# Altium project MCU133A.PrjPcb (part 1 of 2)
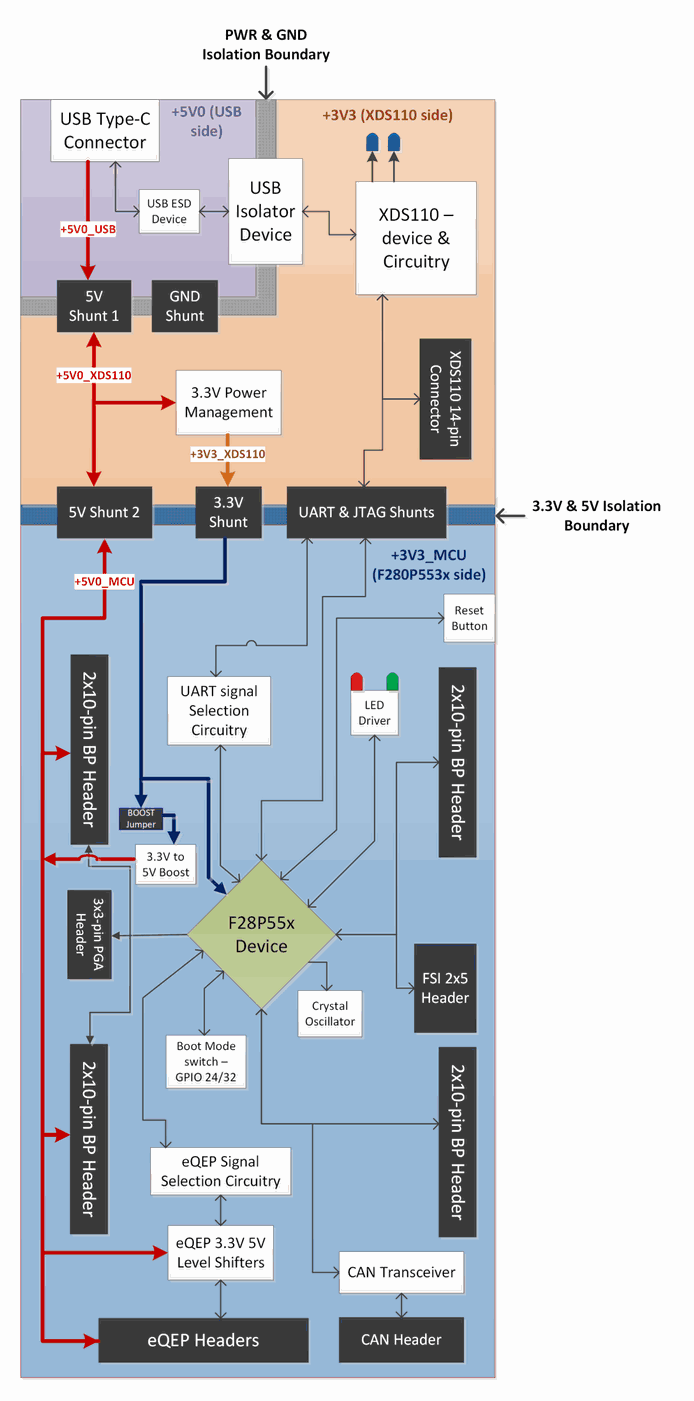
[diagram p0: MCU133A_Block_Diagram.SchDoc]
CopyrightYear: 2024; DrawnBy: Stevan Duraskovic; EVM_orderable: LAUNCHXL-F28P55X; PCB_Layout: a0507455; PCB_Rev: A; PRJ_Customer: Public Release; PRJ_Engineer: Stevan Duraskovic; PRJ_Number: MCU133; PRJ_Title: LAUNCHXL-F28P55X; SCH_Rev: A; TechSupport: http://www.ti.com/support; TID: N/A
8 sheets, 279 parts. Net scope: global (net labels, ports and power ports of the same name join across sheets).
Board file: MCU133A.PcbDoc
Sheets:
  MCU133A_Block_Diagram.SchDoc
  MCU133A_Connectors.SchDoc
  MCU133A_AltRouting_Misc.SchDoc
  MCU133A_F28P55x_Device.SchDoc
  MCU133A_ADC.SchDoc
  MCU133A_USB_and_Power.SchDoc
  MCU133A_XDS110_MCU.SchDoc
  MCU133A_Hardware.SchDoc

## Sheet MCU133A_Block_Diagram.SchDoc
size 431 x 279 mm; Date: Not shown in title block; ApprovedBy: Not shown in title block; CheckedBy: Not shown in title block; Author: Not shown in title block; CompanyName: Not shown in title block; Engineer: Not shown in title block; Organization: Not shown in title block; Address1: Not shown in title block; Address2: Not shown in title block; Address3: Not shown in title block; Address4: Not shown in title block; DocumentNumber: 1; Revision: Use project parameter SCH_Rev; SheetNumber: 1; SheetTotal: 8; PageSetup: Record=PageOptions¦CenterHorizontal=True¦CenterVertical=True¦PrintScale=1.00¦XCorrection=1.00¦YCorrection=1.00¦PrintKind=0¦BorderSize=5000000¦LeftOffset=0¦BottomOffset=0¦Orientation=2¦PaperLength=1000¦PaperWidth=1000¦Scale=100¦PaperSource=15¦PrintQuality=600¦MediaType=1¦DitherType=10¦PaperKind=Letter¦PrintScaleMode=1

## Sheet MCU133A_Connectors.SchDoc
size 431 x 279 mm; Date: Not shown in title block; ApprovedBy: Not shown in title block; CheckedBy: Not shown in title block; Author: Not shown in title block; CompanyName: Not shown in title block; Engineer: Not shown in title block; Organization: Not shown in title block; Address1: Not shown in title block; Address2: Not shown in title block; Address3: Not shown in title block; Address4: Not shown in title block; DocumentNumber: 2; Revision: Use project parameter SCH_Rev; SheetNumber: 2; SheetTotal: 8; PageSetup: Record=PageOptions¦CenterHorizontal=True¦CenterVertical=True¦PrintScale=1.00¦XCorrection=1.00¦YCorrection=1.00¦PrintKind=0¦BorderSize=5000000¦LeftOffset=0¦BottomOffset=0¦Orientation=2¦PaperLength=1000¦PaperWidth=1000¦Scale=100¦PaperSource=15¦PrintQuality=600¦MediaType=1¦DitherType=10¦PaperKind=Letter¦PrintScaleMode=1
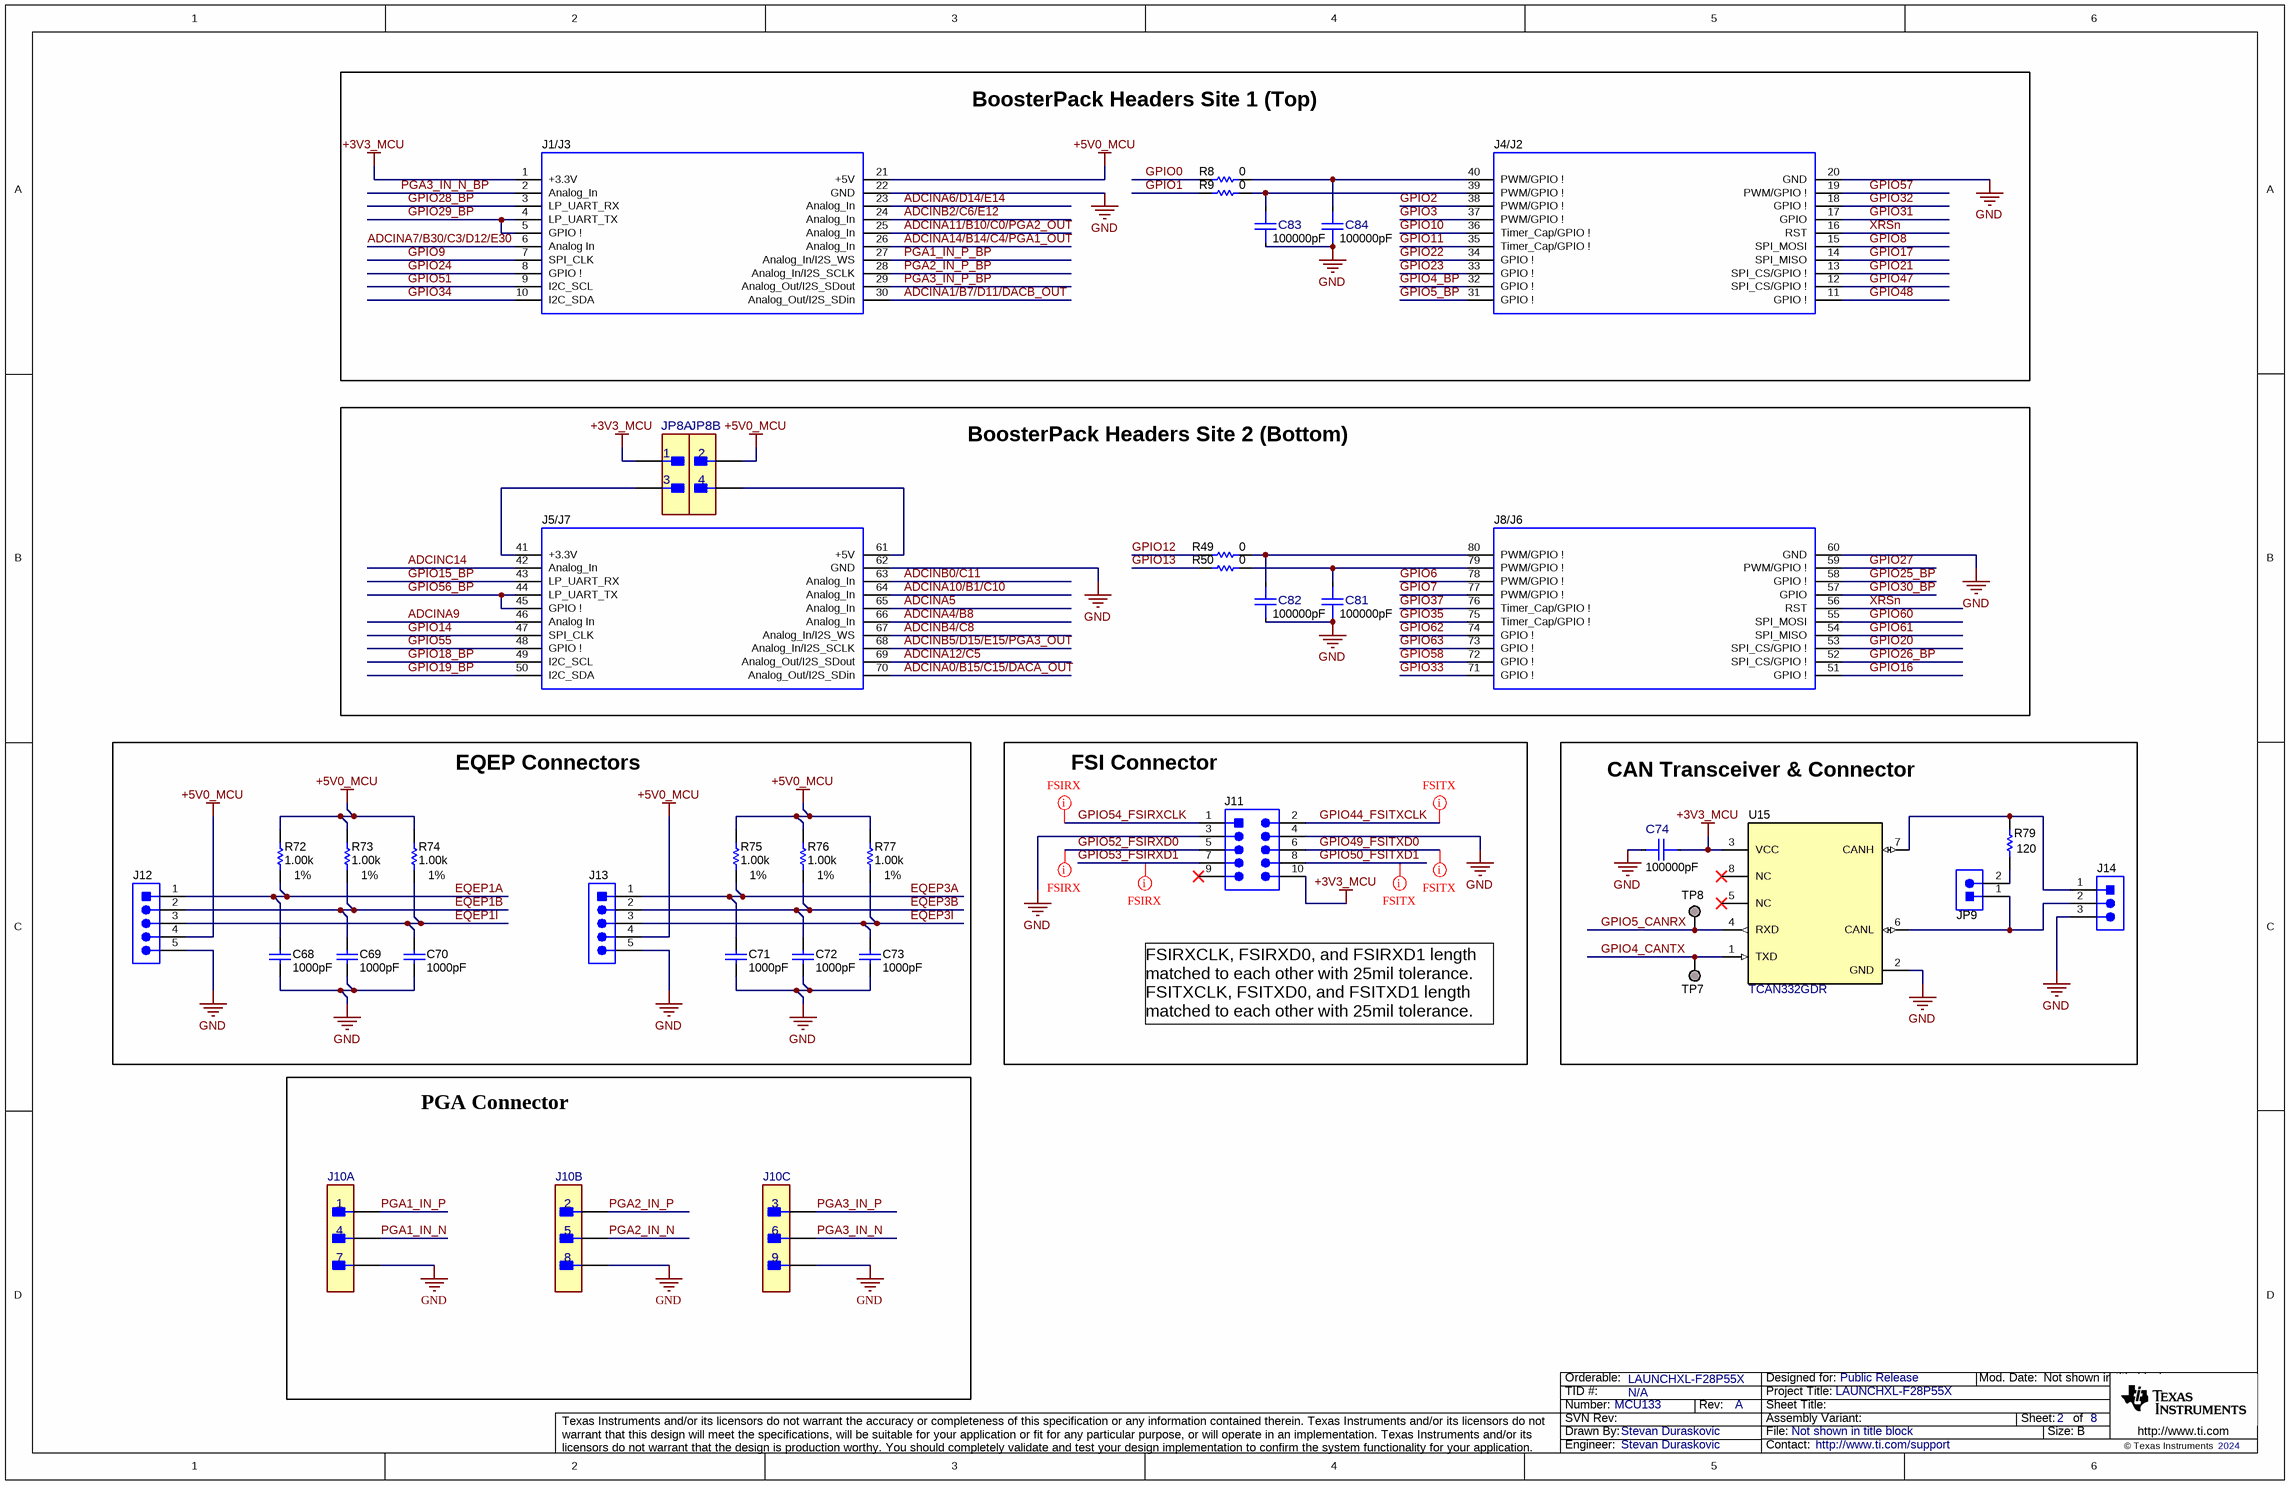
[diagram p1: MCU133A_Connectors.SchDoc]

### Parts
C68  ValueDisplayed: 1000pF  [0402]  (hidden comment: 885012205061)
C69  ValueDisplayed: 1000pF  [0402]  (hidden comment: 885012205061)
C70  ValueDisplayed: 1000pF  [0402]  (hidden comment: 885012205061)
C71  ValueDisplayed: 1000pF  [0402]  (hidden comment: 885012205061)
C72  ValueDisplayed: 1000pF  [0402]  (hidden comment: 885012205061)
C73  ValueDisplayed: 1000pF  [0402]  (hidden comment: 885012205061)
C74  ValueDisplayed: 100000pF  [FP-885012205018_0402-MFG]  (hidden comment: 885012205018)
C81  ValueDisplayed: 100000pF  [FP-885012205018_0402-MFG]  (hidden comment: 885012205018)
C82  ValueDisplayed: 100000pF  [FP-885012205018_0402-MFG]  (hidden comment: 885012205018)
C83  ValueDisplayed: 100000pF  [FP-885012205018_0402-MFG]  (hidden comment: 885012205018)
C84  ValueDisplayed: 100000pF  [FP-885012205018_0402-MFG]  (hidden comment: 885012205018)
J1/J3  SSQ-110-03-T-D  [BoosterPack_40pin_J1J3]  (value not drawn)
J4/J2  SSQ-110-03-T-D  [BoosterPack_40pin_J2J4]  (value not drawn)
J5/J7  SSQ-110-03-T-D  [BoosterPack_40pin_J5J7]  (value not drawn)
J8/J6  SSQ-110-03-T-D  [BoosterPack_40pin_J6J8]  (value not drawn)
J10  TSW-103-07-G-T  [FP-TSW-103-07-G-T_HDR9-MFG]  (value not drawn)  (parts A,B,C of 3)
J11  61301021121  [WURTH_61301021121]  (value not drawn)
J12  61300511121  [Wurth_61300511121]  (value not drawn)
J13  61300511121  [Wurth_61300511121]  (value not drawn)
J14  61300311121  [WURTH_61300311121]  (value not drawn)
JP8  61300421121  [FP-61300421121_HDR4-MFG]  (value not drawn)  (parts A,B of 2)
JP9  61300211121  [WURTH_61300211121]  (value not drawn)
R8  ValueDisplayed: 0  [0402]  (hidden comment: RC0402JR-070RL)
R9  ValueDisplayed: 0  [0402]  (hidden comment: RC0402JR-070RL)
R49  ValueDisplayed: 0  [0402]  (hidden comment: RC0402JR-070RL)
R50  ValueDisplayed: 0  [0402]  (hidden comment: RC0402JR-070RL)
R72  ValueDisplayed: 1.00k  Value1: 1%  [0402]  (hidden comment: CRCW04021K00FKED)
R73  ValueDisplayed: 1.00k  Value1: 1%  [0402]  (hidden comment: CRCW04021K00FKED)
R74  ValueDisplayed: 1.00k  Value1: 1%  [0402]  (hidden comment: CRCW04021K00FKED)
R75  ValueDisplayed: 1.00k  Value1: 1%  [0402]  (hidden comment: CRCW04021K00FKED)
R76  ValueDisplayed: 1.00k  Value1: 1%  [0402]  (hidden comment: CRCW04021K00FKED)
R77  ValueDisplayed: 1.00k  Value1: 1%  [0402]  (hidden comment: CRCW04021K00FKED)
R79  RC0603FR-07120RL  [0603]  (value not drawn)
TP7  TESTPOINT  [TP_50MIL-25MILHOLE]  (value not drawn)  (no BOM)
TP8  TESTPOINT  [TP_50MIL-25MILHOLE]  (value not drawn)  (no BOM)
U15  TCAN332GDR  [D0008A_N]

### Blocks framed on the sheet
BoosterPack Headers Site 1 (Top): C83 C84 J1/J3 J4/J2 R8 R9
BoosterPack Headers Site 2 (Bottom): C81 C82 J5/J7 J8/J6 JP8 R49 R50
EQEP Connectors: C68-C73 J12 J13 R72-R77
FSI Connector: J11
CAN Transceiver & Connector: C74 J14 JP9 R79 TP7 TP8 U15

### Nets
+3V3_MCU: C74.1 J1/J3.1(+3.3V) J11.10 JP8.1 U15.3(VCC)
+5V0_MCU: J1/J3.21(+5V) J12.4 J13.4 JP8.2 R72.2 R73.2 R74.2 R75.2 R76.2 R77.2
GND: C68.2 C69.2 C70.2 C71.2 C72.2 C73.2 C74.2 C81.1 C82.1 C83.1 C84.1 J1/J3.22(GND) J4/J2.20(GND) J5/J7.62(GND) J8/J6.60(GND) J10.7 J10.8 J10.9 J11.3 J11.4 J12.5 J13.5 J14.3 U15.2(GND)
ADCINA0/B15/C15/DACA_OUT: J5/J7.70(Analog_Out/I2S_SDin)
ADCINA1/B7/D11/DACB_OUT: J1/J3.30(Analog_Out/I2S_SDin)
ADCINA4/B8: J5/J7.66(Analog_In)
ADCINA5: J5/J7.65(Analog_In)
ADCINA6/D14/E14: J1/J3.23(Analog_In)
ADCINA7/B30/C3/D12/E30: J1/J3.6(Analog_In)
ADCINA9: J5/J7.46(Analog_In)
ADCINA10/B1/C10: J5/J7.64(Analog_In)
ADCINA11/B10/C0/PGA2_OUT: J1/J3.25(Analog_In)
ADCINA12/C5: J5/J7.69(Analog_Out/I2S_SDout)
ADCINA14/B14/C4/PGA1_OUT: J1/J3.26(Analog_In)
ADCINB0/C11: J5/J7.63(Analog_In)
ADCINB2/C6/E12: J1/J3.24(Analog_In)
ADCINB4/C8: J5/J7.67(Analog_In/I2S_WS)
ADCINB5/D15/E15/PGA3_OUT: J5/J7.68(Analog_In/I2S_SCLK)
ADCINC14: J5/J7.42(Analog_In)
EQEP1A: C68.1 J12.1 R72.1
EQEP1B: C69.1 J12.2 R73.1
EQEP1I: C70.1 J12.3 R74.1
EQEP3A: C71.1 J13.1 R75.1
EQEP3B: C72.1 J13.2 R76.1
EQEP3I: C73.1 J13.3 R77.1
GPIO0: R8.1
GPIO1: R9.1
GPIO2: J4/J2.38(PWM/GPIO_!)
GPIO3: J4/J2.37(PWM/GPIO_!)
GPIO4_BP: J4/J2.32(GPIO_!)
GPIO4_CANTX: TP7.1 U15.1(TXD)
GPIO5_BP: J4/J2.31(GPIO_!)
GPIO5_CANRX: TP8.1 U15.4(RXD)
GPIO6: J8/J6.78(PWM/GPIO_!)
GPIO7: J8/J6.77(PWM/GPIO_!)
GPIO8: J4/J2.15(SPI_MOSI)
GPIO9: J1/J3.7(SPI_CLK)
GPIO10: J4/J2.36(Timer_Cap/GPIO_!)
GPIO11: J4/J2.35(Timer_Cap/GPIO_!)
GPIO12: R49.1
GPIO13: R50.1
GPIO14: J5/J7.47(SPI_CLK)
GPIO15_BP: J5/J7.43(LP_UART_RX)
GPIO16: J8/J6.51(GPIO_!)
GPIO17: J4/J2.14(SPI_MISO)
GPIO18_BP: J5/J7.49(I2C_SCL)
GPIO19_BP: J5/J7.50(I2C_SDA)
GPIO20: J8/J6.53(SPI_CS/GPIO_!)
GPIO21: J4/J2.13(SPI_CS/GPIO_!)
GPIO22: J4/J2.34(GPIO_!)
GPIO23: J4/J2.33(GPIO_!)
GPIO24: J1/J3.8(GPIO_!)
GPIO25_BP: J8/J6.58(GPIO_!)
GPIO26_BP: J8/J6.52(SPI_CS/GPIO_!)
GPIO27: J8/J6.59(PWM/GPIO_!)
GPIO28_BP: J1/J3.3(LP_UART_RX)
GPIO29_BP: J1/J3.4(LP_UART_TX) J1/J3.5(GPIO_!)
GPIO30_BP: J8/J6.57(GPIO)
GPIO31: J4/J2.17(GPIO)
GPIO32: J4/J2.18(GPIO_!)
GPIO33: J8/J6.71(GPIO_!)
GPIO34: J1/J3.10(I2C_SDA)
GPIO35: J8/J6.75(Timer_Cap/GPIO_!)
GPIO37: J8/J6.76(Timer_Cap/GPIO_!)
GPIO44_FSITXCLK: J11.2
GPIO47: J4/J2.12(SPI_CS/GPIO_!)
GPIO48: J4/J2.11(GPIO_!)
GPIO49_FSITXD0: J11.6
GPIO50_FSITXD1: J11.8
GPIO51: J1/J3.9(I2C_SCL)
GPIO52_FSIRXD0: J11.5
GPIO53_FSIRXD1: J11.7
GPIO54_FSIRXCLK: J11.1
GPIO55: J5/J7.48(GPIO_!)
GPIO56_BP: J5/J7.44(LP_UART_TX) J5/J7.45(GPIO_!)
GPIO57: J4/J2.19(PWM/GPIO_!)
GPIO58: J8/J6.72(GPIO_!)
GPIO60: J8/J6.55(SPI_MOSI)
GPIO61: J8/J6.54(SPI_MISO)
GPIO62: J8/J6.74(GPIO_!)
GPIO63: J8/J6.73(GPIO_!)
PGA1_IN_N: J10.4
PGA1_IN_P: J10.1
PGA1_IN_P_BP: J1/J3.27(Analog_In/I2S_WS)
PGA2_IN_N: J10.5
PGA2_IN_P: J10.2
PGA2_IN_P_BP: J1/J3.28(Analog_In/I2S_SCLK)
PGA3_IN_N: J10.6
PGA3_IN_N_BP: J1/J3.2(Analog_In)
PGA3_IN_P: J10.3
PGA3_IN_P_BP: J1/J3.29(Analog_Out/I2S_SDout)
XRSn: J4/J2.16(RST) J8/J6.56(RST)
NetC81_2: C81.2 J8/J6.79(PWM/GPIO_!) R50.2
NetC82_2: C82.2 J8/J6.80(PWM/GPIO_!) R49.2
NetC83_2: C83.2 J4/J2.39(PWM/GPIO_!) R9.2
NetC84_2: C84.2 J4/J2.40(PWM/GPIO_!) R8.2
NetJ5/J7_41: J5/J7.41(+3.3V) JP8.3
NetJ5/J7_61: J5/J7.61(+5V) JP8.4
NetJ14_1: J14.1 R79.2 U15.7(CANH)
NetJ14_2: J14.2 JP9.1 U15.6(CANL)
NetJP9_2: JP9.2 R79.1

Not connected (* = marked no-connect by the designer): J11 9*; U15 5(NC)* 8(NC)*

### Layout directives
net class FSIRX: GPIO52_FSIRXD0, GPIO53_FSIRXD1, GPIO54_FSIRXCLK
net class FSITX: GPIO44_FSITXCLK, GPIO49_FSITXD0, GPIO50_FSITXD1

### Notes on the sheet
- (near R79) 120
- FSIRXCLK, FSIRXD0, and FSIRXD1 length matched to each other with 25mil tolerance.
  FSITXCLK, FSITXD0, and FSITXD1 length matched to each other with 25mil tolerance.
- PGA Connector

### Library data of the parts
C68-C73 = CMP-0006231-2: CAP, CERM, 1000 pF, 50 V, +/- 10%, X7R, 0402; Manufacturer: Wurth Elektronik; Polarized: N; Value: 1000pF; U/M: EA; Cap_F: 1nF; Value1: Unknown; VDC_V: 50V; TaMin_C: -55°C; TaMax_C: 125°C; SizeArea_mm2: 0.5; SizeAreaWB_mm2: 3; SizeX_mm: 1; SizeZ_mm: 0.6; AEC Category: Q200
C74 C81-C84 = CMP-0090362-1: 0.1µF ±10% 10V Ceramic Capacitor X7R 0402 (1005 Metric); Manufacturer: Wurth Electronics; AEC Qualified: No; Value: 100nF; SizeZ_mm: 0.55mm; TempCo: 15%
J1/J3 = CMP-0003837-4: Receptacle, 2.54mm, 10x2, Tin, TH; Alternate PartNumber: CRD-081413-A-G; Manufacturer: Samtec; Alternate Manufacturer: Major League Electronics; Note: Booster Pack 40 pin J1 and J3; Green_Lifecycle: Active; Green_REACh: Incomplete
J4/J2 = CMP-0078266-4: Receptacle, 2.54mm, 10x2, Tin, TH; Alternate PartNumber: CRD-081413-A-G; Manufacturer: Samtec; Alternate Manufacturer: Major League Electronics; Note: Booster Pack 40 pin J2 and J4; Green_REACh: Incomplete; Green_Lifecycle: Active
J5/J7 = CMP-0081070-3: Receptacle, 2.54mm, 10x2, Tin, TH; Alternate PartNumber: CRD-081413-A-G; Manufacturer: Samtec; Alternate Manufacturer: Major League Electronics; Note: Booster Pack 40 pin J5 and J7; Green_REACh: Incomplete; Green_Lifecycle: Active
J8/J6 = CMP-0081071-3: Receptacle, 2.54mm, 10x2, Tin, TH; Alternate PartNumber: CRD-081413-A-G; Manufacturer: Samtec; Alternate Manufacturer: Major League Electronics; Note: Booster Pack 40 pin J6 and J8; Green_REACh: Incomplete; Green_Lifecycle: Active
J10 = CMP-0090263-1: Manufacturer: Samtec; Conn Gender: Male; AEC Qualified: No; Conn Orientation: Straight; DUT-Pitch_mm: 2.54mm; Row_Count: 3; SizeZ_mm: 8.64mm; ContactFinish: Gold,Nickel
J11 = CMP-0054806-3: Header, 2.54 mm, 5x2, Gold, TH; Manufacturer: Wurth Elektronik; Green_Lifecycle: Active; Green_REACh: Passed; Cert_UL: Y; Current_A: 3A; Gender: Male; Pitch_mm: 2.54; Row_Count: 2; Shrouded: N; Voltage_V: 250V
J12 J13 = CMP-0084909-1: Header, 2.54mm, 5x1, Gold, TH; Manufacturer: Wurth Elektronik; Pitch_mm: 2.54; Gender: Male; Row_Count: 1; Shrouded: N; Current_A: 3A; Voltage_V: 250V
J14 = CMP-0054796-1: Header, 2.54 mm, 3x1, Gold, TH; Manufacturer: Wurth Elektronik; Green_Lifecycle: Active; Green_REACh: Passed; CNHeader: TRUE; CT: FALSE
JP8 = CMP-0092422-1: THT Vertical Pin Header WR-PHD, Pitch 2.54 mm, Dual Row, 4 pins; Manufacturer: Wurth Electronics; DUT-Pitch_mm: 2.54mm; SizeZ_mm: 8.89mm; Voltage_V: 250V; Conn Gender: Male; AEC Qualified: No; Row_Count: 2; ContactFinish: Gold; Conn Orientation: Straight; Current_A: 3A
JP9 = CMP-0054794-1: Header, 2.54 mm, 2x1, Gold, TH; Manufacturer: Wurth Elektronik; Green_Lifecycle: Active; Green_REACh: Passed; CNHeader: TRUE; CT: FALSE
R8 R9 R49 R50 = CMP-0027004-2: RES, 0, 5%, 0.063 W, 0402; Manufacturer: Yageo America; Power_W: 63mW; TempCo: 200 ppm/C; Value_Code: 0000; U/M: EA; Value: 0; EIA_Code: E24; SizeX_mm: 1; SizeY_mm: 0.5; SizeZ_mm: 0.6; Value2: 0.063W; VDC_V: 50V; AEC Category: Q200
R72-R77 = CMP-0026071-3: RES, 1.00 k, 1%, 0.063 W, AEC-Q200 Grade 0, 0402; Manufacturer: Vishay-Dale; Value: 1.00k; Res_ohm: 1k; Value_Code: 1k00; Power_W: 63mW; Value2: 0.063W; VDC_V: 50V; TempCo: 100 ppm/C; SizeArea_mm2: 0.5; SizeX_mm: 1; SizeZ_mm: 0.6; EIA_Code: E96; AEC Category: Q200; AEC Qualified: Y; AEC Grade: 0
R79 = CMP-0022769-3: RES, 120, 1%, 0.1 W, 0603; Manufacturer: Yageo America; Value: 120; Value_Code: 120R; Power_W: 100mW; Value2: 0.1W; VDC_V: 150V; TempCo: 200 ppm/C; SizeArea_mm2: 1.28; SizeX_mm: 1.6; SizeY_mm: 0.8; SizeZ_mm: 1; U/M: EA; AEC Category: Q200
TP7 TP8 = CMP-0078143-3: TEST POINT.  No entry in BOM.
U15 = CMP-0080978-2: 3.3-V CAN Transceivers with CAN FD (Flexible Data Rate), D0008A (SOIC-8); Alternate Manufacturer: Texas Instruments; SizeAreaWB_mm2: 56.58; SizeZ_mm: 1.75; SizeX_mm: 4.9; SizeY_mm: 6.2; SizeArea_mm2: 30.38; CompType: IC; AEC Qualified: N; AEC Category: Q200

## Sheet MCU133A_AltRouting_Misc.SchDoc
size 431 x 279 mm; Date: Not shown in title block; ApprovedBy: Not shown in title block; CheckedBy: Not shown in title block; Author: Not shown in title block; CompanyName: Not shown in title block; Engineer: Not shown in title block; Organization: Not shown in title block; Address1: Not shown in title block; Address2: Not shown in title block; Address3: Not shown in title block; Address4: Not shown in title block; DocumentNumber: 3; Revision: Use project parameter SCH_Rev; SheetNumber: 3; SheetTotal: 8; PageSetup: Record=PageOptions¦CenterHorizontal=True¦CenterVertical=True¦PrintScale=1.00¦XCorrection=1.00¦YCorrection=1.00¦PrintKind=0¦BorderSize=5000000¦LeftOffset=0¦BottomOffset=0¦Orientation=2¦PaperLength=1000¦PaperWidth=1000¦Scale=100¦PaperSource=15¦PrintQuality=600¦MediaType=1¦DitherType=10¦PaperKind=Letter¦PrintScaleMode=1
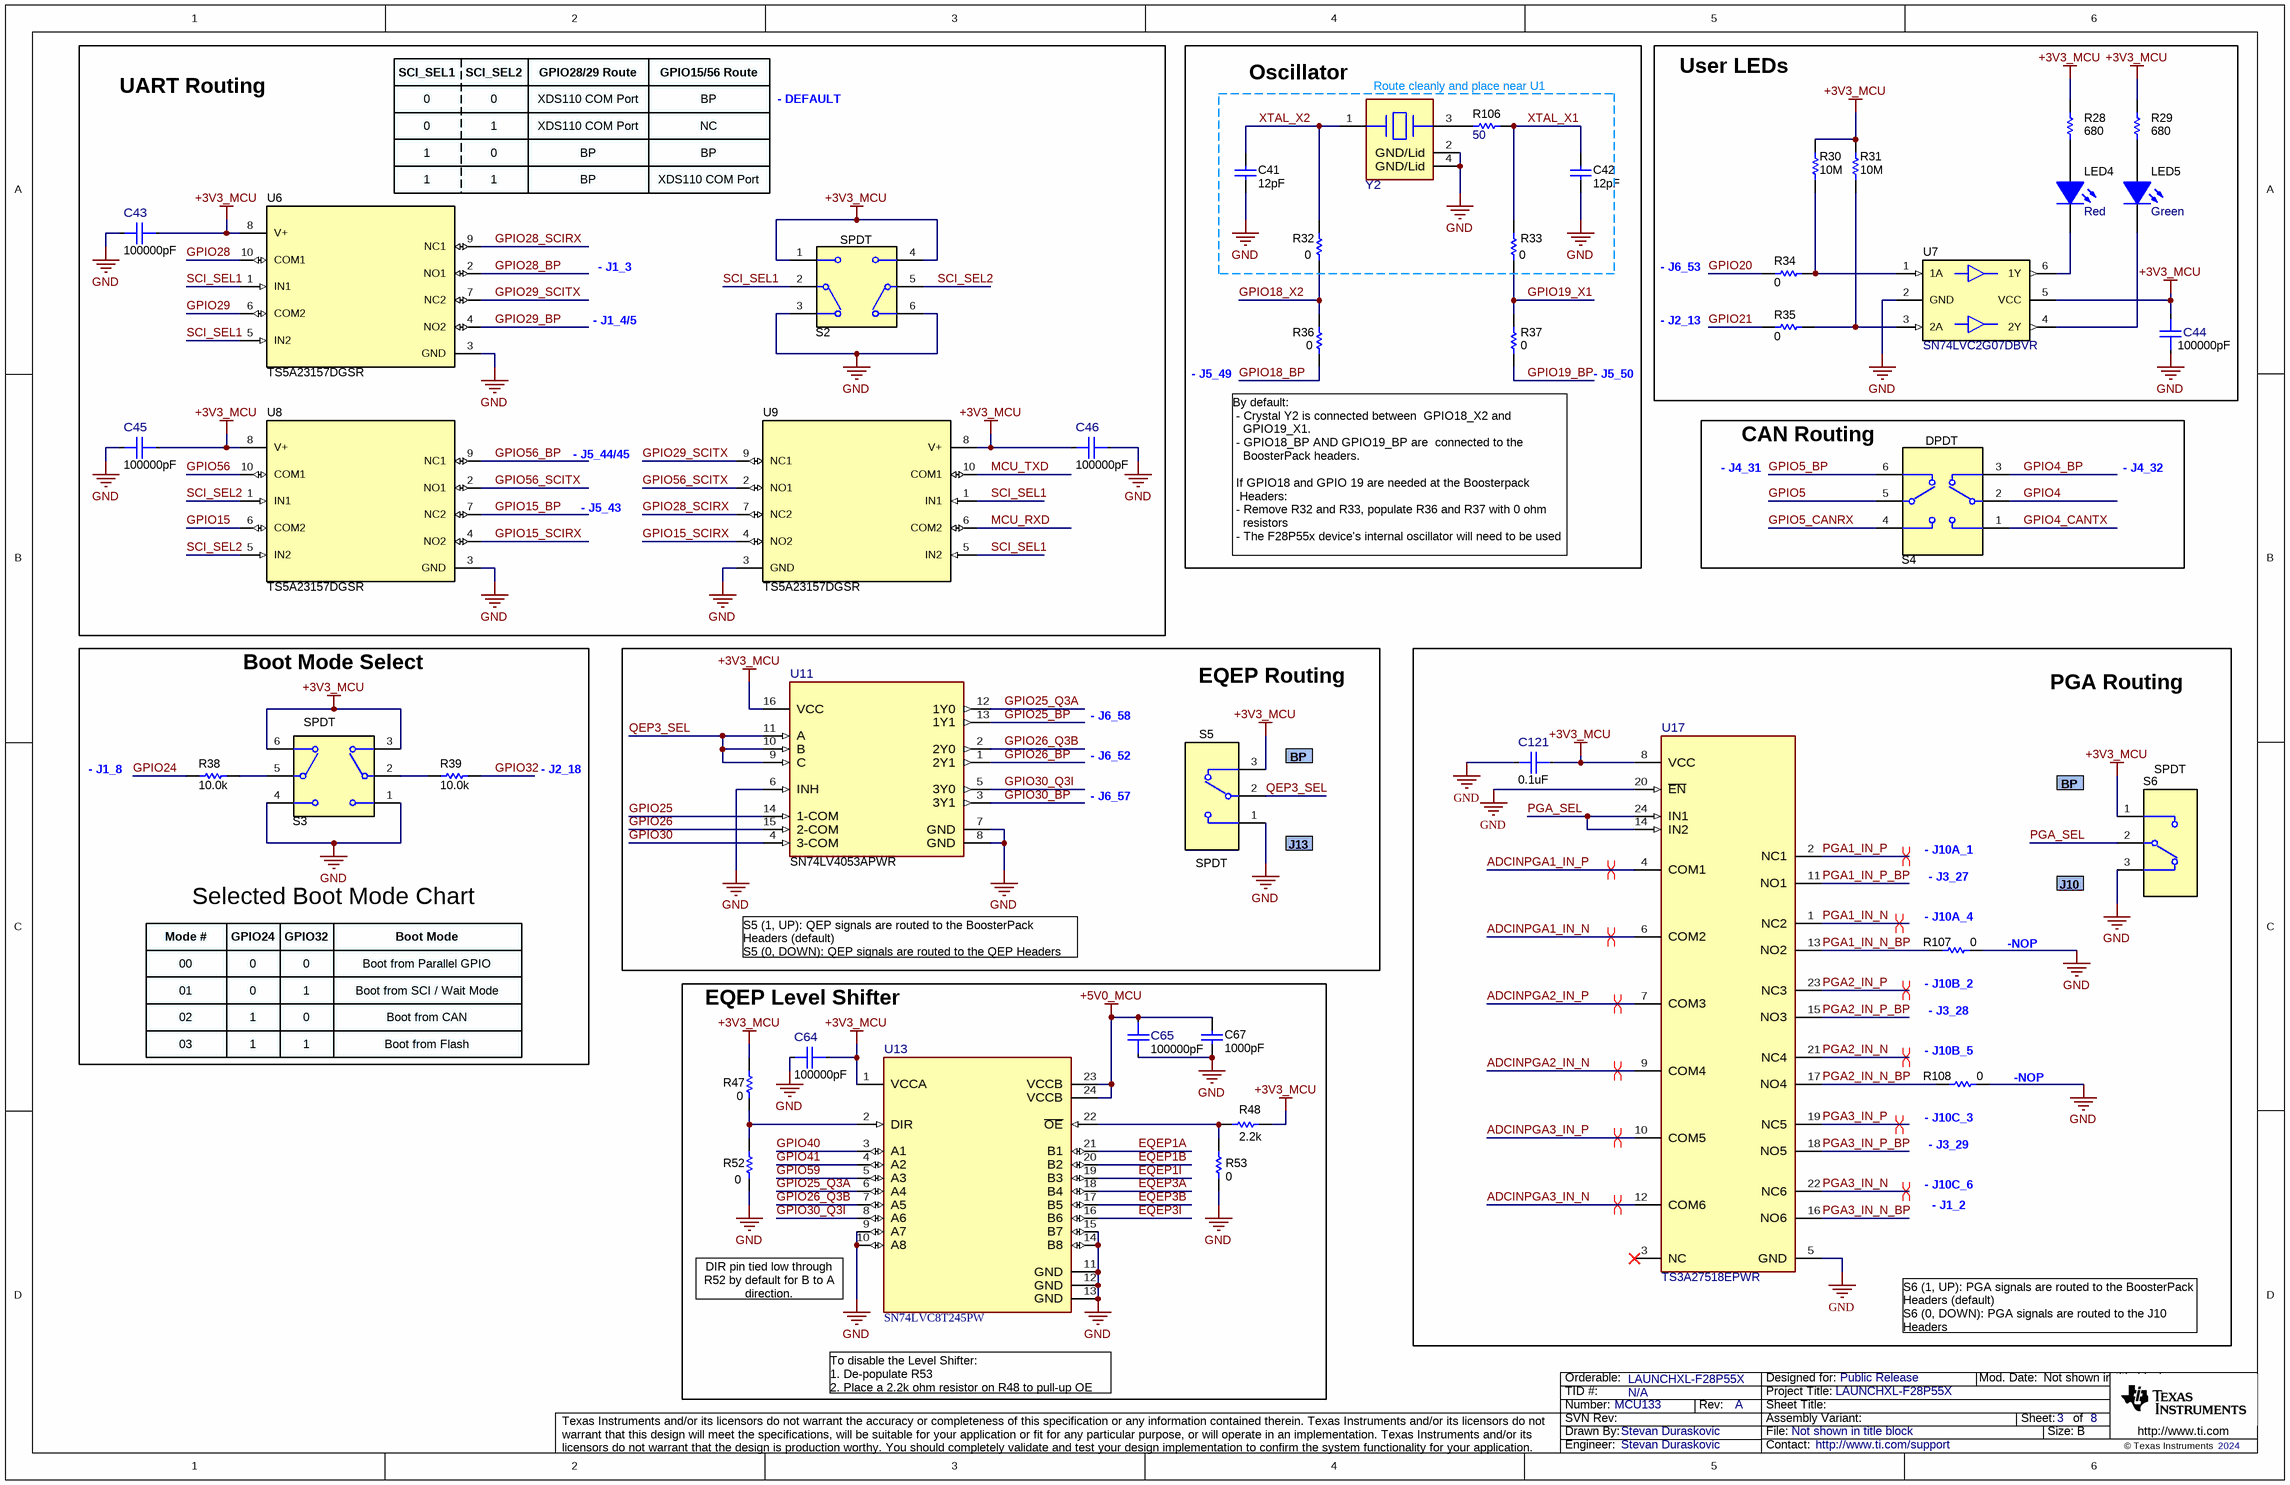
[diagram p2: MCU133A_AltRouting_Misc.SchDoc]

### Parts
C41  ValueDisplayed: 12pF  [0402]  (hidden comment: C0402C120J3GACAUTO)
C42  ValueDisplayed: 12pF  [0402]  (hidden comment: C0402C120J3GACAUTO)
C43  ValueDisplayed: 100000pF  [FP-885012205018_0402-MFG]  (hidden comment: 885012205018)
C44  ValueDisplayed: 100000pF  [FP-885012205018_0402-MFG]  (hidden comment: 885012205018)
C45  ValueDisplayed: 100000pF  [FP-885012205018_0402-MFG]  (hidden comment: 885012205018)
C46  ValueDisplayed: 100000pF  [FP-885012205018_0402-MFG]  (hidden comment: 885012205018)
C64  ValueDisplayed: 100000pF  [FP-885012205018_0402-MFG]  (hidden comment: 885012205018)
C65  ValueDisplayed: 100000pF  [FP-885012205018_0402-MFG]  (hidden comment: 885012205018)
C67  ValueDisplayed: 1000pF  [0402]  (hidden comment: 885012205061)
C121  ValueDisplayed: 0.1uF  [FP-885012205018_0402-MFG]  (hidden comment: 885012205018)
LED4  value Red  [WL-SMCW_RED_0805]  (hidden comment: 150080SS75000)
LED5  value Green  [LED_LTST-C171]  (hidden comment: LTST-C171GKT)
R28  ValueDisplayed: 680  [0402]  (hidden comment: CRCW0402680RJNED)
R29  ValueDisplayed: 680  [0402]  (hidden comment: CRCW0402680RJNED)
R30  ValueDisplayed: 10M  [0402]  (hidden comment: CRCW040210M0JNED)
R31  ValueDisplayed: 10M  [0402]  (hidden comment: CRCW040210M0JNED)
R32  ValueDisplayed: 0  [0603]  (hidden comment: CRCW06030000Z0EA)
R33  ValueDisplayed: 0  [0603]  (hidden comment: CRCW06030000Z0EA)
R34  ValueDisplayed: 0  [0603]  (hidden comment: CRCW06030000Z0EA)
R35  ValueDisplayed: 0  [0603]  (hidden comment: CRCW06030000Z0EA)
R36  ValueDisplayed: 0  [0603]  (hidden comment: CRCW06030000Z0EA)
R37  ValueDisplayed: 0  [0603]  (hidden comment: CRCW06030000Z0EA)
R38  ValueDisplayed: 10.0k  [0603]  (hidden comment: RC0603FR-0710KL)
R39  ValueDisplayed: 10.0k  [0603]  (hidden comment: RC0603FR-0710KL)
R47  ValueDisplayed: 0  [0603]  (hidden comment: CRCW06030000Z0EA)
R48  ValueDisplayed: 2.2k  [0603]  (hidden comment: CRCW06032K20JNEA)
R52  ValueDisplayed: 0  [0603]  (hidden comment: CRCW06030000Z0EA)
R53  ValueDisplayed: 0  [0603]  (hidden comment: CRCW06030000Z0EA)
R106  ValueDisplayed: 50  [0603]  (hidden comment: FC0603E50R0BTBST1)
R107  ValueDisplayed: 0  [0603]  (hidden comment: CRCW06030000Z0EA)
R108  ValueDisplayed: 0  [0603]  (hidden comment: CRCW06030000Z0EA)
S2  CAS-D20TA  [SW_CAS-D20TA]  (value not drawn)
S3  CAS-D20TA  [SW_CAS-D20TA]  (value not drawn)
S4  CAS-220TA  [SW_CAS-220TA]  (value not drawn)
S5  CAS-120TA  [SW_CAS-120TA]  (value not drawn)
S6  CAS-120TA  [SW_CAS-120TA]  (value not drawn)
U6  TS5A23157DGSR  [DGS0010A_N]
U7  SN74LVC2G07DBVR  [DBV0006A_N]
U8  TS5A23157DGSR  [DGS0010A_N]
U9  TS5A23157DGSR  [DGS0010A_N]
U11  SN74LV4053APWR  [PW0016A-MFG]
U13  SN74LVC8T245PW  [PW0024A-MFG]
U17  TS3A27518EPWR  [PW0024A-MFG]
Y2  830108207209  [FP-830108207209_SMT_CRYSTAL_3MM2_2MM5-MFG]  (value not drawn)

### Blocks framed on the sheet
UART Routing: C43 C45 C46 S2 U6 U8 U9
Oscillator: C41 C42 R32 R33 R36 R37 R106 Y2
User LEDs: C44 LED4 LED5 R28-R31 R34 R35 U7
CAN Routing: S4
Selected Boot Mode Chart: R38 R39 S3
EQEP Routing: S5 U11
PGA Routing: C121 R107 R108 S6 U17
EQEP Level Shifter: C64 C65 C67 R47 R48 R52 R53 U13

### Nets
+3V3_MCU: C43.1 C44.2 C45.1 C46.2 C64.1 C121.1 R28.2 R29.2 R30.2 R31.2 R47.2 R48.2 S2.1 S2.4 S3.3 S3.6 S5.3 S6.1 U6.8(V+) U7.5(VCC) U8.8(V+) U9.8(V+) U11.16(VCC) U13.1(VCCA) U17.8(VCC)
+5V0_MCU: C65.2 C67.1 U13.23(VCCB) U13.24(VCCB)
GND: C41.2 C42.2 C43.2 C44.1 C45.2 C46.1 C64.2 C65.1 C67.2 C121.2 R52.1 R53.2 R107.2 R108.2 S2.3 S2.6 S3.1 S3.4 S5.1 S6.3 U6.3(GND) U7.2(GND) U8.3(GND) U9.3(GND) U11.6(INH) U11.7(GND) U11.8(GND) U13.9(A7) U13.10(A8) U13.11(GND) U13.12(GND) U13.13(GND) U13.14(B8) U13.15(B7) U17.5(GND) U17.20(~{EN}) Y2.2(GND/Lid) Y2.4(GND/Lid)
ADCINPGA1_IN_N: U17.6(COM2)
ADCINPGA1_IN_P: U17.4(COM1)
ADCINPGA2_IN_N: U17.9(COM4)
ADCINPGA2_IN_P: U17.7(COM3)
ADCINPGA3_IN_N: U17.12(COM6)
ADCINPGA3_IN_P: U17.10(COM5)
EQEP1A: U13.21(B1)
EQEP1B: U13.20(B2)
EQEP1I: U13.19(B3)
EQEP3A: U13.18(B4)
EQEP3B: U13.17(B5)
EQEP3I: U13.16(B6)
GPIO4: S4.2
GPIO4_BP: S4.3
GPIO4_CANTX: S4.1
GPIO5: S4.5
GPIO5_BP: S4.6
GPIO5_CANRX: S4.4
GPIO15: U8.6(COM2)
GPIO15_BP: U8.7(NC2)
GPIO15_SCIRX: U8.4(NO2) U9.4(NO2)
GPIO18_BP: R36.1
GPIO18_X2: R32.1 R36.2
GPIO19_BP: R37.1
GPIO19_X1: R33.1 R37.2
GPIO20: R34.1
GPIO21: R35.1
GPIO24: R38.1
GPIO25: U11.14(1-COM)
GPIO25_BP: U11.13(1Y1)
GPIO25_Q3A: U11.12(1Y0) U13.6(A4)
GPIO26: U11.15(2-COM)
GPIO26_BP: U11.1(2Y1)
GPIO26_Q3B: U11.2(2Y0) U13.7(A5)
GPIO28: U6.10(COM1)
GPIO28_BP: U6.2(NO1)
GPIO28_SCIRX: U6.9(NC1) U9.7(NC2)
GPIO29: U6.6(COM2)
GPIO29_BP: U6.4(NO2)
GPIO29_SCITX: U6.7(NC2) U9.9(NC1)
GPIO30: U11.4(3-COM)
GPIO30_BP: U11.3(3Y1)
GPIO30_Q3I: U11.5(3Y0) U13.8(A6)
GPIO32: R39.2
GPIO40: U13.3(A1)
GPIO41: U13.4(A2)
GPIO56: U8.10(COM1)
GPIO56_BP: U8.9(NC1)
GPIO56_SCITX: U8.2(NO1) U9.2(NO1)
GPIO59: U13.5(A3)
MCU_RXD: U9.6(COM2)
MCU_TXD: U9.10(COM1)
PGA1_IN_N: U17.1(NC2)
PGA1_IN_N_BP: R107.1 U17.13(NO2)
PGA1_IN_P: U17.2(NC1)
PGA1_IN_P_BP: U17.11(NO1)
PGA2_IN_N: U17.21(NC4)
PGA2_IN_N_BP: R108.1 U17.17(NO4)
PGA2_IN_P: U17.23(NC3)
PGA2_IN_P_BP: U17.15(NO3)
PGA3_IN_N: U17.22(NC6)
PGA3_IN_N_BP: U17.16(NO6)
PGA3_IN_P: U17.19(NC5)
PGA3_IN_P_BP: U17.18(NO5)
PGA_SEL: S6.2 U17.14(IN2) U17.24(IN1)
QEP3_SEL: S5.2 U11.9(C) U11.10(B) U11.11(A)
SCI_SEL1: S2.2(C) U6.1(IN1) U6.5(IN2) U9.1(IN1) U9.5(IN2)
SCI_SEL2: S2.5(C) U8.1(IN1) U8.5(IN2)
XTAL_X1: C42.1 R33.2 R106.2
XTAL_X2: C41.1 R32.2 Y2.1(1_Crystal)
NetLED4_1: LED4.1(K) U7.6(1Y)
NetLED4_2: LED4.2(A) R28.1
NetLED5_1: LED5.1(A) R29.1
NetLED5_2: LED5.2(K) U7.4(2Y)
NetR30_1: R30.1 R34.2 U7.1(1A)
NetR31_1: R31.1 R35.2 U7.3(2A)
NetR38_2: R38.2 S3.5(C)
NetR39_1: R39.1 S3.2(C)
NetR47_1: R47.1 R52.2 U13.2(DIR)
NetR48_1: R48.1 R53.1 U13.22(~{OE})
NetR106_1: R106.1 Y2.3(2_Crystal)

Not connected (* = marked no-connect by the designer): U17 3(NC)*

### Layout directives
differential pair: ADCINPGA1_IN_N, ADCINPGA1_IN_P, ADCINPGA2_IN_N, ADCINPGA2_IN_P, ADCINPGA3_IN_N, ADCINPGA3_IN_P, PGA1_IN_N, PGA1_IN_P, PGA2_IN_N, PGA2_IN_P, PGA3_IN_N, PGA3_IN_P

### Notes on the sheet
- SCI_SEL1
- 0
- SCI_SEL2
- GPIO28/29 Route
- XDS110 COM Port
- GPIO15/56 Route
- BP
- - DEFAULT
- Route cleanly and place near U1
- 1
- NC
- (near U6) 1
- - J1_3
- (near S2) SPDT
- - J6_53
- - J1_4/5
- - J2_13
- - J5_49
- - J5_50
- (near S4) DPDT
- - J5_44/45
- - J4_31
- - J4_32
- - J5_43
- By default:
  - Crystal Y2 is connected between  GPIO18_X2 and
  GPIO19_X1.
  - GPIO18_BP AND GPIO19_BP are  connected to the
  BoosterPack headers.
  If GPIO18 and GPIO 19 are needed at the Boosterpack
  Headers:
  - Remove R32 and R33, populate R36 and R37 with 0 ohm
  resistors
  - The F28P55x device's internal oscillator will need to be used
- Boot Mode Select
- - J1_8
- (near S3) SPDT
- - J2_18
- - J6_58
- - J6_52
- (near S5) BP
- (near S6) SPDT
- - J6_57
- (near S5) SPDT
- (near S5) J13
- - J3_27
- - J10A_1
- J10
- Mode #
- 00
- GPIO24
- GPIO32
- Boot Mode
- Boot from Parallel GPIO
- S5 (1, UP): QEP signals are routed to the BoosterPack Headers (default)
  S5 (0, DOWN): QEP signals are routed to the QEP Headers
- (near R107) - J10A_4
- (near R107) -NOP
- 01
- 02
- Boot from SCI / Wait Mode
- Boot from CAN
- - J3_28
- (near R107) - J10B_2
- 03
- Boot from Flash
- (near R108) - J10B_5
- (near R108) -NOP
- - J3_29
- (near R108) - J10C_3
- - J10C_6
- - J1_2
- (near U13) DIR pin tied low through R52 by default for B to A direction.
- S6 (1, UP): PGA signals are routed to the BoosterPack Headers (default)
  S6 (0, DOWN): PGA signals are routed to the J10 Headers
- To disable the Level Shifter:
  1. De-populate R53
  2. Place a 2.2k ohm resistor on R48 to pull-up OE

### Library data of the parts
C41 C42 = CMP-0006239-2: CAP, CERM, 12 pF, 25 V, +/- 5%, C0G/NP0, AEC-Q200 Grade 1, 0402; Manufacturer: Kemet; TaMin_C: -55°C; Polarized: N; SizeAreaWB_mm2: 3; Value1: Unknown; U/M: EA; Value: 12pF; TaMax_C: 125°C; SizeZ_mm: 0.6; SizeX_mm: 1; SizeY_mm: 0.5; Value2: 25V; AEC Qualified: Y; AEC Category: Q200
C43-C46 C64 C65 C121 = CMP-0090362-1: as C74 on sheet MCU133A_Connectors
C67 = CMP-0006231-2: as C68 on sheet MCU133A_Connectors
LED4 = CMP-0002951-3: LED, Red, SMD; Manufacturer: Wurth Elektronik; Type: AlInGaP; Vf_V: 1.9V; Io_A: 30mA; Vr_V: 5V; Ir_A: 25µA; Tjmax_C: 85°C; Power_TotalModule: 72mW; Value1: 0.072W; Angle: 140
LED5 = CMP-0002830-3: LED, Green, SMD; Manufacturer: Lite-On; Type: AlInGaP; Vf_V: 2.1V; Io_A: 20A; Value1: W; SizeAreaWB_mm2: 6.75; SizeArea_mm2: 2.5; SizeX_mm: 2; SizeY_mm: 1.25; SizeZ_mm: 1.2
R28 R29 = CMP-0026962-3: RES, 680, 5%, 0.063 W, AEC-Q200 Grade 0, 0402; Manufacturer: Vishay-Dale; Power_W: 63mW; TempCo: 200 ppm/C; Value_Code: 680R; Value: 680; EIA_Code: E24; SizeX_mm: 1; SizeY_mm: 0.5; SizeZ_mm: 0.6; Value2: 0.063W; AEC Qualified: Y; VDC_V: 50V; AEC Category: Q200; AEC Grade: 0
R30 R31 = CMP-0026826-2: RES, 10 M, 5%, 0.063 W, AEC-Q200 Grade 0, 0402; Manufacturer: Vishay-Dale; Value: 10Meg; Value_Code: 10M0; Power_W: 63mW; Value2: 0.063W; VDC_V: 50V; TempCo: 200 ppm/C; SizeArea_mm2: 0.5; SizeX_mm: 1; SizeZ_mm: 0.6; EIA_Code: E24; AEC Category: Q200; AEC Qualified: Y; AEC Grade: 0
R32-R37 R47 R52 R53 R107 R108 = CMP-0025697-4: RES, 0, 5%, 0.1 W, AEC-Q200 Grade 0, 0603; Manufacturer: Vishay-Dale; Value: 0; Value_Code: 0000; Power_W: 100mW; Value2: 0.1W; VDC_V: 75V; TempCo: 200 ppm/C; SizeArea_mm2: 1.28; SizeX_mm: 1.6; SizeY_mm: 0.8; SizeZ_mm: 1; EIA_Code: E24; AEC Category: Q200; AEC Qualified: Y
R38 R39 = CMP-0022746-5: RES, 10.0 k, 1%, 0.1 W, 0603; Manufacturer: Yageo; Power_W: 100mW; TempCo: 100 ppm/C; Value_Code: 10k0; Value: 10.0k; EIA_Code: E96; Res_ohm: 10k; SizeX_mm: 1.6; SizeY_mm: 0.8; SizeZ_mm: 1; Value2: 0.1W; SizeArea_mm2: 1.28; AEC Qualified: N; VDC_V: 75V; AEC Category: Q200; SizeAreaWB_mm2: 4.68
R48 = CMP-0025769-4: RES, 2.2 k, 5%, 0.1 W, AEC-Q200 Grade 0, 0603; Manufacturer: Vishay-Dale; Value: 2.2k; Value_Code: 2k20; Power_W: 100mW; Value2: 0.1W; VDC_V: 75V; TempCo: 200 ppm/C; SizeArea_mm2: 1.28; SizeX_mm: 1.6; SizeY_mm: 0.8; SizeZ_mm: 1; EIA_Code: E24; AEC Category: Q200; AEC Qualified: Y; AEC Grade: 0
R106 = CMP-0023387-3: RES, 50, 0.1%, 0.125 W, 0603; Manufacturer: Vishay Thin Film; Power_W: 125mW; TempCo: 25 ppm/C; Value_Code: 50R0; U/M: EA; Value: 50; SizeX_mm: 1.6; SizeY_mm: 0.8; SizeZ_mm: 1; Value2: 0.125W; SizeArea_mm2: 1.28; AEC Qualified: N; VDC_V: 50V; AEC Category: Q200
S2 = CMP-0002233-1: Switch, Dual SPDT,  2 Pos, 0.1A, 6VDC, SMD; Manufacturer: Copal Electronics; VDC_V: 6V; SwitchFunction: On-On; PositionCount: 2; CurrentRating_mA: 100A
S3 = CMP-0002233-1: Switch, Dual SPDT,  2 Pos, 0.1A, 6VDC, SMD; Manufacturer: Copal Electronics; CurrentRating_mA: 100A; SwitchFunction: On-On; VDC_V: 6V; PositionCount: 2
S4 = CMP-0002123-2: SLIDE SWITCH DPDT  .1A, SMT; Manufacturer: Copal Electronics; VDC_V: 6V; SwitchFunction: On-On; PositionCount: 2; CurrentRating_mA: 100A
S5 S6 = CMP-0002139-2: Switch, Slide, SPDT  100mA, SMT; Manufacturer: Copal Electronics; CurrentRating_mA: 100A; SwitchFunction: On-On; VDC_V: 6V; PositionCount: 1
U6 U8 U9 = CMP-0067418-1: DUAL 10-Ohm SPDT ANALOG SWITCH, DGS0010A (VSSOP-10); Alternate PartNumber: TS5A23157DGST; Alternate Manufacturer: Texas Instruments; Green_Lifecycle: Active; SizeAreaWB_mm2: 23.6; Green_REACh: Passed; U/M: EA; SizeZ_mm: 1.1; SizeX_mm: 4.9; SizeY_mm: 3.0; SizeArea_mm2: 14.7; CompType: IC
U7 = CMP-0051789-2: Dual Buffer/Driver with Open-Drain Output, DBV0006A, LARGE T&R; Manufacturer: Texas Instruments; VCC(Min)(V): 1.65; VCC(Max)(V): 5.5; Output Type: CMOS; ICC @ Nom Voltage(Max)(mA): 0.01; Input Type: CMOS/TTL; Bits(#): 2; F @ Nom Voltage(Max)(Mhz): 150; Rating: Catalog; Technology Family: LVC; Voltage(Nom)(V): 1.8,2.5,3.3,5; Schmitt Trigger: No; Output Drive (IOL/IOH)(Max)(mA): 32/-32; tpd @ Nom Voltage(Max)(ns): 8.6,4.4,3.7,2.9; Logic: True; Sub-Family: Inverting Buffer/Driver; AEC Category: Q200; AEC Qualified: N; CompType: IC; Green_Lifecycle: Active; Green_REACh: Passed; SizeArea_mm2: 8.12; SizeAreaWB_mm2: 14.82; SizeX_mm: 2.8; SizeY_mm: 2.9; SizeZ_mm: 1.45
U11 = CMP-0089841-1: 3 Circuit IC Switch 2:1 75Ohm 16-TSSOP; Manufacturer: Texas Instruments; TaMax_C: +85°C; Max Supply Voltage: 5.5V; PositionCount: 3; AEC Qualified: No; SizeZ_mm: 1.2mm; Standoff Height: 0.05mm; On State Resistance: 100-225Ω; Min Supply Voltage: 2V; -3Db Bandwith: 50MHz; Nominal Supply Current: 20uA; TaMin_C: -40°C
U13 = CMP-0121414-1: 8-Bit Dual-Supply Bus Transceiver With Configurable Voltage Translation and 3-State Outputs; Manufacturer: Texas Instruments; SizeZ_mm: 1.2mm; AEC Qualified: No; Data Rate: 200Mbits/s; Logic Function: Non-Inverting; Nominal Supply Current: 25uA; Number Of Inputs: 8; PositionCount: 1; Propagation Delay: 4.3ns; Standoff Height: 0.05mm; TaMax_C: +85°C; TaMin_C: -40°C; TJmax_C: +150°C; V A Max: 5.5V; V A Min: 1.65V
U17 = CMP-0092155-1: 3.3-V, 2:1 (SPDT), 6-channel analog multiplexer with 1.8-V compatible control inputs 24-TSSOP -40 to 85; Manufacturer: Texas Instruments; Max Supply Voltage: 3.6V; -3Db Bandwith: 240MHz; Standoff Height: 0.05mm; Category 9E37533Dafe045F0: Logic, Standard; SizeZ_mm: 1.2mm; On State Resistance: 4.4Ω; Category Aef863F29A99753F: Switches; AEC Qualified: No; Category 9E07530Daf1645C0: Semiconductors and Actives; Min Supply Voltage: 1.65V; Nominal Supply Current: 0.01-0.04uA; PositionCount: 6
Y2 = CMP-0093781-1: 20 MHz ±10ppm Crystal 8pF 50 Ohms 4-SMD, No Lead; Manufacturer: Wurth Electronics; SizeZ_mm: 0.8mm; Frequency Stability: 20ppm; Esr: 50; Frequency_Fixed: 20MHz

## Sheet MCU133A_F28P55x_Device.SchDoc
size 431 x 279 mm; Date: Not shown in title block; ApprovedBy: Not shown in title block; CheckedBy: Not shown in title block; Author: Not shown in title block; CompanyName: Not shown in title block; Engineer: Not shown in title block; Organization: Not shown in title block; Address1: Not shown in title block; Address2: Not shown in title block; Address3: Not shown in title block; Address4: Not shown in title block; DocumentNumber: 4; Revision: Use project parameter SCH_Rev; SheetNumber: 4; SheetTotal: 8; PageSetup: Record=PageOptions¦CenterHorizontal=True¦CenterVertical=True¦PrintScale=1.00¦XCorrection=1.00¦YCorrection=1.00¦PrintKind=0¦BorderSize=5000000¦LeftOffset=0¦BottomOffset=0¦Orientation=2¦PaperLength=1000¦PaperWidth=1000¦Scale=100¦PaperSource=15¦PrintQuality=600¦MediaType=1¦DitherType=10¦PaperKind=Letter¦PrintScaleMode=1
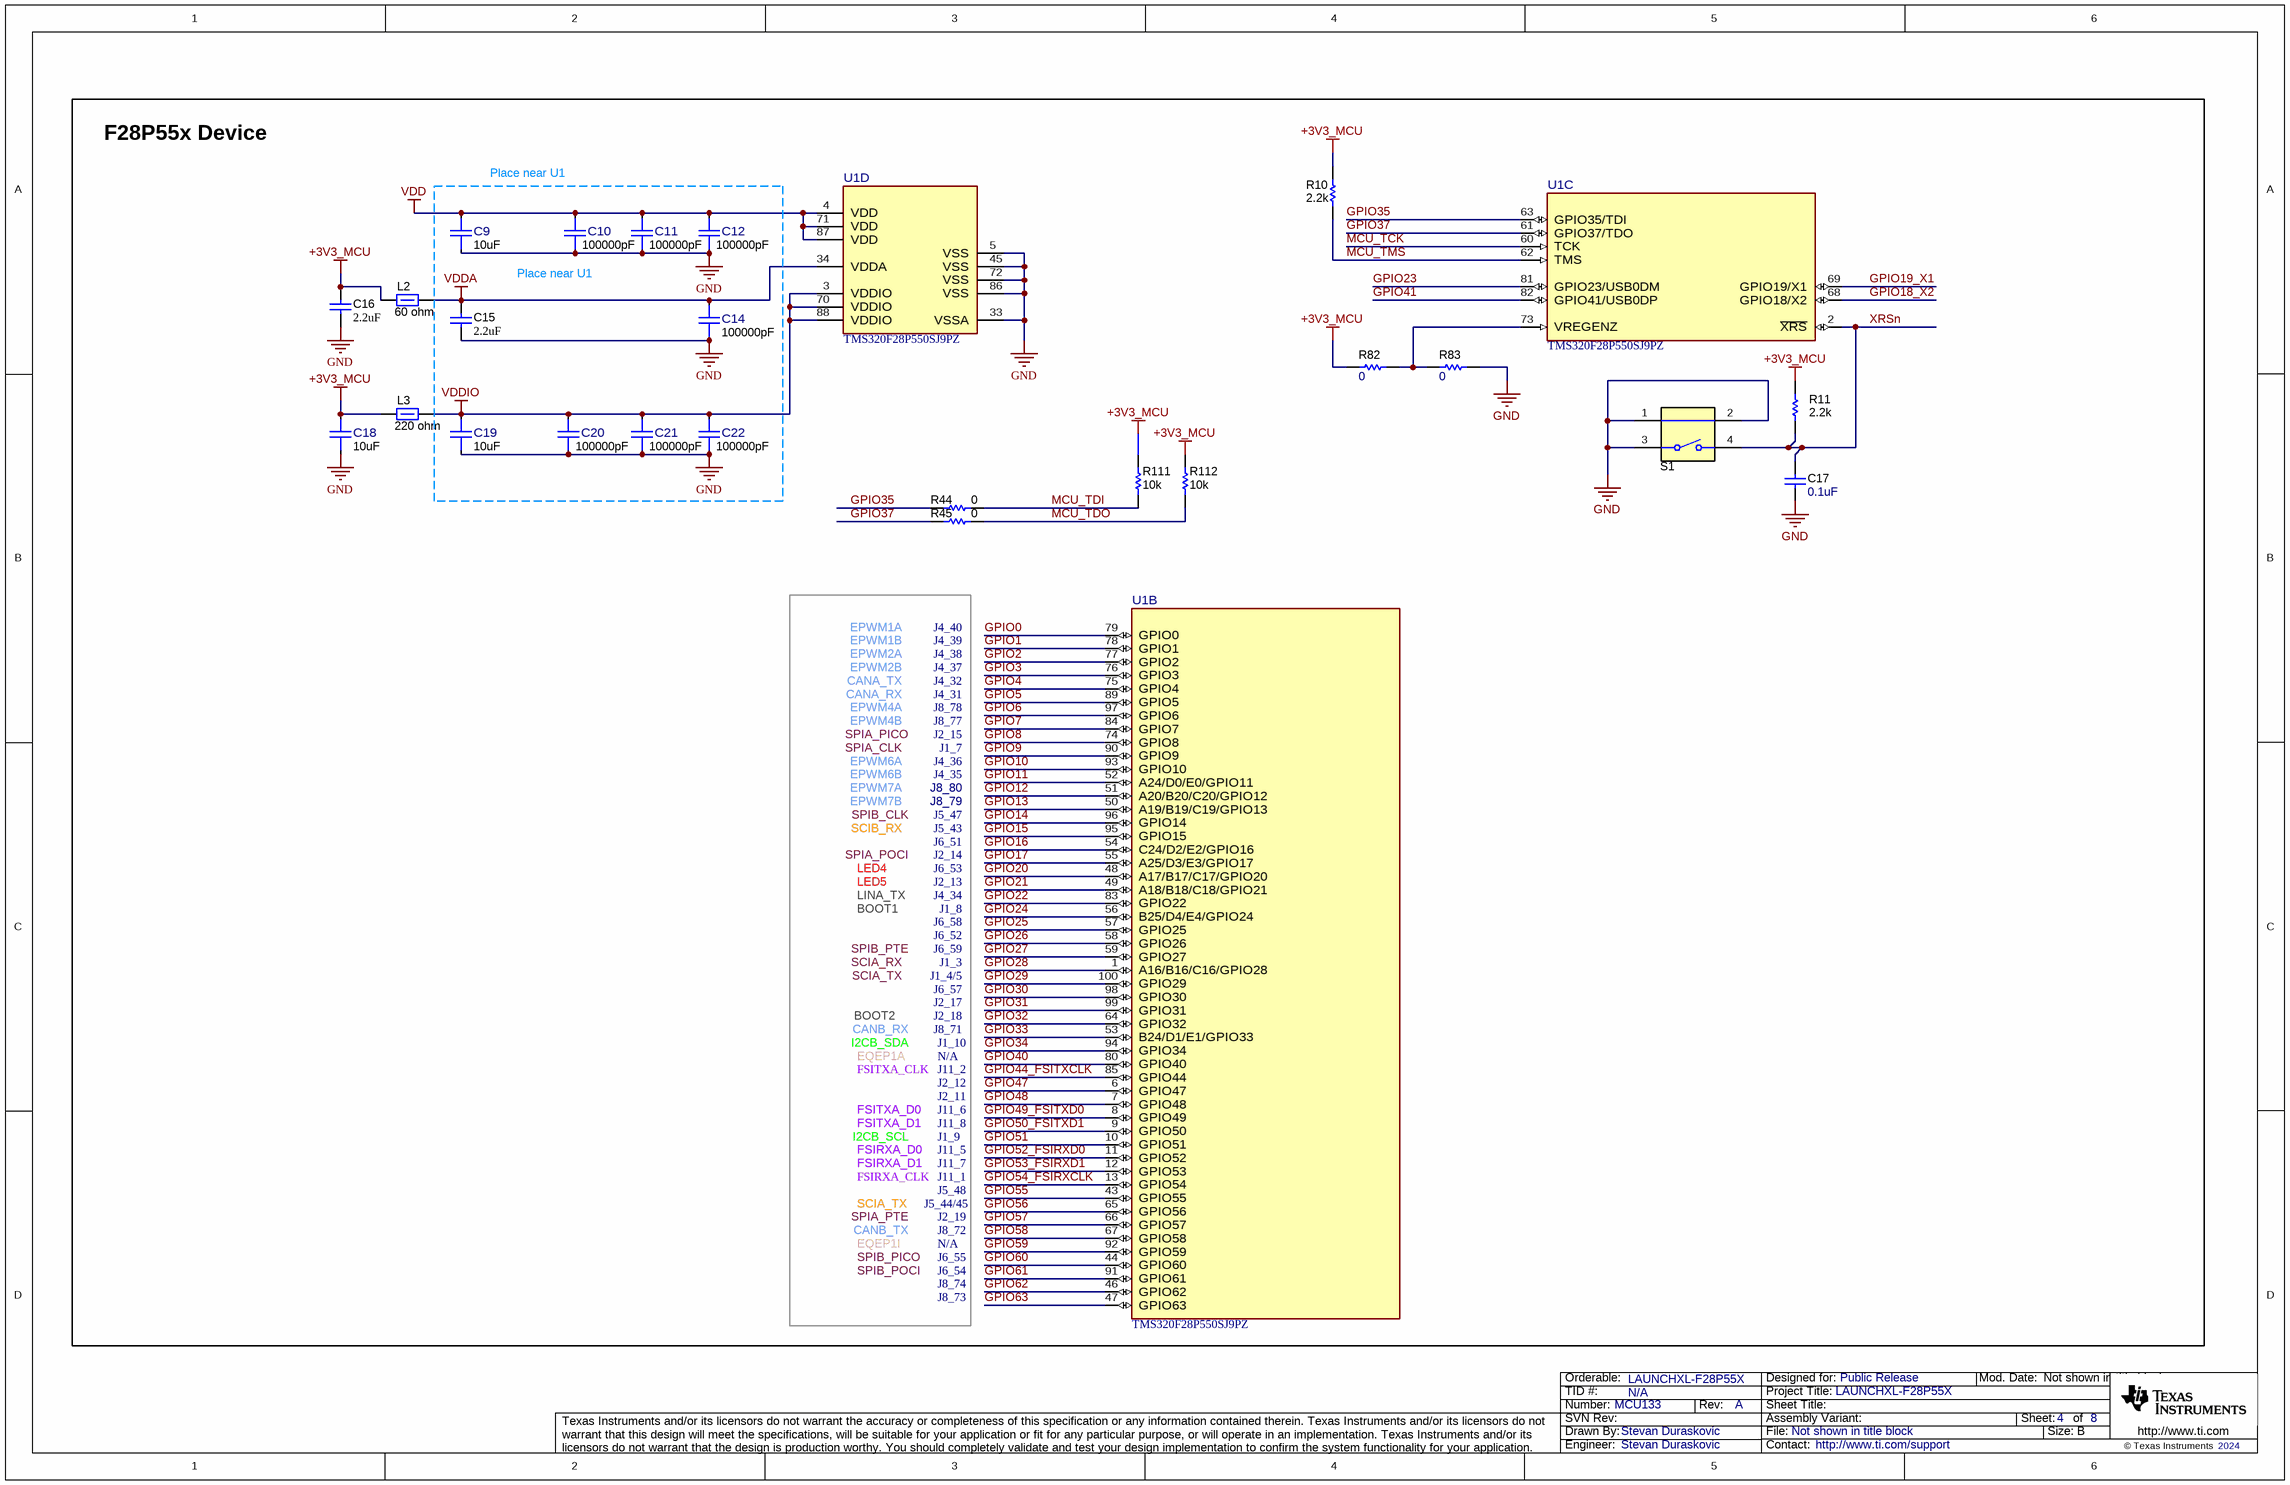
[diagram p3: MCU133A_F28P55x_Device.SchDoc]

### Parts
C9  ValueDisplayed: 10uF  [FP-CC0603KRX5R6BB106_0603-MFG]  (hidden comment: CC0603KRX5R6BB106)
C10  ValueDisplayed: 100000pF  [FP-885012205018_0402-MFG]  (hidden comment: 885012205018)
C11  ValueDisplayed: 100000pF  [FP-885012205018_0402-MFG]  (hidden comment: 885012205018)
C12  ValueDisplayed: 100000pF  [FP-885012205018_0402-MFG]  (hidden comment: 885012205018)
C14  ValueDisplayed: 100000pF  [FP-885012205018_0402-MFG]  (hidden comment: 885012205018)
C15  ValueDisplayed: 2.2uF  [0603]  (hidden comment: CGA3E3X5R1A225K080AB)
C16  ValueDisplayed: 2.2uF  [0603]  (hidden comment: CGA3E3X5R1A225K080AB)
C17  ValueDisplayed: 0.1uF  [0402]  (hidden comment: 885012205037)
C18  ValueDisplayed: 10uF  [FP-CC0603KRX5R6BB106_0603-MFG]  (hidden comment: CC0603KRX5R6BB106)
C19  ValueDisplayed: 10uF  [FP-CC0603KRX5R6BB106_0603-MFG]  (hidden comment: CC0603KRX5R6BB106)
C20  ValueDisplayed: 100000pF  [FP-885012205018_0402-MFG]  (hidden comment: 885012205018)
C21  ValueDisplayed: 100000pF  [FP-885012205018_0402-MFG]  (hidden comment: 885012205018)
C22  ValueDisplayed: 100000pF  [FP-885012205018_0402-MFG]  (hidden comment: 885012205018)
L2  value 60 ohm  [0805_HV]  (hidden comment: 742792063)
L3  ValueDisplayed: 220 ohm  [0805_HV]  (hidden comment: 742792022)
R10  ValueDisplayed: 2.2k  [0402]  (hidden comment: CRCW04022K20JNED)
R11  ValueDisplayed: 2.2k  [0402]  (hidden comment: CRCW04022K20JNED)
R44  ValueDisplayed: 0  [0402]  (hidden comment: RC0402JR-070RL)
R45  ValueDisplayed: 0  [0402]  (hidden comment: RC0402JR-070RL)
R82  ValueDisplayed: 0  [0402]  (hidden comment: ERJ-2GE0R00X)
R83  ValueDisplayed: 0  [0402]  (hidden comment: ERJ-2GE0R00X)
R111  ValueDisplayed: 10k  [0402]  (hidden comment: RC0402JR-070RL)
R112  ValueDisplayed: 10k  [0402]  (hidden comment: RC0402JR-070RL)
S1  1188E-1K2-V-TR  [SW_1188E]  (value not drawn)
U1  TMS320F28P550SJ9PZ  [PZ0100A-MFG]  (parts B,C,D of 4)

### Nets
+3V3_MCU: C16.1 C18.2 L2.1 L3.1 R10.2 R11.2 R82.1 R111.2 R112.2
GND: C9.1 C10.1 C11.1 C12.1 C14.1 C15.2 C16.2 C17.2 C18.1 C19.1 C20.1 C21.1 C22.1 R83.2 S1.1 S1.2 S1.3 U1.5(VSS) U1.33(VSSA) U1.45(VSS) U1.72(VSS) U1.86(VSS)
VDD: C9.2 C10.2 C11.2 C12.2 U1.4(VDD) U1.71(VDD) U1.87(VDD)
VDDA: C14.2 C15.1 L2.2 U1.34(VDDA)
VDDIO: C19.2 C20.2 C21.2 C22.2 L3.2 U1.3(VDDIO) U1.70(VDDIO) U1.88(VDDIO)
GPIO0: U1.79(GPIO0)
GPIO1: U1.78(GPIO1)
GPIO2: U1.77(GPIO2)
GPIO3: U1.76(GPIO3)
GPIO4: U1.75(GPIO4)
GPIO5: U1.89(GPIO5)
GPIO6: U1.97(GPIO6)
GPIO7: U1.84(GPIO7)
GPIO8: U1.74(GPIO8)
GPIO9: U1.90(GPIO9)
GPIO10: U1.93(GPIO10)
GPIO11: U1.52(A24/D0/E0/GPIO11)
GPIO12: U1.51(A20/B20/C20/GPIO12)
GPIO13: U1.50(A19/B19/C19/GPIO13)
GPIO14: U1.96(GPIO14)
GPIO15: U1.95(GPIO15)
GPIO16: U1.54(C24/D2/E2/GPIO16)
GPIO17: U1.55(A25/D3/E3/GPIO17)
GPIO18_X2: U1.68(GPIO18/X2)
GPIO19_X1: U1.69(GPIO19/X1)
GPIO20: U1.48(A17/B17/C17/GPIO20)
GPIO21: U1.49(A18/B18/C18/GPIO21)
GPIO22: U1.83(GPIO22)
GPIO23: U1.81(GPIO23/USB0DM)
GPIO24: U1.56(B25/D4/E4/GPIO24)
GPIO25: U1.57(GPIO25)
GPIO26: U1.58(GPIO26)
GPIO27: U1.59(GPIO27)
GPIO28: U1.1(A16/B16/C16/GPIO28)
GPIO29: U1.100(GPIO29)
GPIO30: U1.98(GPIO30)
GPIO31: U1.99(GPIO31)
GPIO32: U1.64(GPIO32)
GPIO33: U1.53(B24/D1/E1/GPIO33)
GPIO34: U1.94(GPIO34)
GPIO35: R44.1 U1.63(GPIO35/TDI)
GPIO37: R45.1 U1.61(GPIO37/TDO)
GPIO40: U1.80(GPIO40)
GPIO41: U1.82(GPIO41/USB0DP)
GPIO44_FSITXCLK: U1.85(GPIO44)
GPIO47: U1.6(GPIO47)
GPIO48: U1.7(GPIO48)
GPIO49_FSITXD0: U1.8(GPIO49)
GPIO50_FSITXD1: U1.9(GPIO50)
GPIO51: U1.10(GPIO51)
GPIO52_FSIRXD0: U1.11(GPIO52)
GPIO53_FSIRXD1: U1.12(GPIO53)
GPIO54_FSIRXCLK: U1.13(GPIO54)
GPIO55: U1.43(GPIO55)
GPIO56: U1.65(GPIO56)
GPIO57: U1.66(GPIO57)
GPIO58: U1.67(GPIO58)
GPIO59: U1.92(GPIO59)
GPIO60: U1.44(GPIO60)
GPIO61: U1.91(GPIO61)
GPIO62: U1.46(GPIO62)
GPIO63: U1.47(GPIO63)
MCU_TCK: U1.60(TCK)
MCU_TDI: R44.2 R111.1
MCU_TDO: R45.2 R112.1
MCU_TMS: R10.1 U1.62(TMS)
XRSn: C17.1 R11.1 S1.4 U1.2(~{XRS})
NetR82_2: R82.2 R83.1 U1.73(VREGENZ)

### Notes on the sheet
- F28P55x Device
- Place near U1
- (near C10) Place near U1
- EPWM1A
- J4_40
- CANA_TX
- CANA_RX
- EPWM1B
- EPWM2A
- EPWM2B
- J4_39
- J4_38
- J4_37
- J4_31
- J4_32
- SPIA_CLK
- EPWM6A
- EPWM4A
- EPWM4B
- SPIA_PICO
- J4_36
- J2_15
- J1_7
- J8_78
- J8_77
- SCIB_RX
- EPWM6B
- EPWM7A
- EPWM7B
- SPIB_CLK
- J4_35
- J5_43
- J8_80
- J5_47
- J8_79
- LINA_TX
- LED4
- LED5
- SPIA_POCI
- J4_34
- J6_51
- J2_14
- J6_53
- J2_13
- BOOT1
- SCIA_RX
- SPIB_PTE
- J6_58
- J6_52
- J6_59
- J1_8
- J1_3
- BOOT2
- SCIA_TX
- CANB_RX
- J1_4/5
- J6_57
- J2_17
- J2_18
- J8_71
- EQEP1A
- FSITXA_CLK
- I2CB_SDA
- J2_11
- J1_10
- N/A
- J2_12
- J11_2
- FSITXA_D0
- FSITXA_D1
- FSIRXA_D0
- FSIRXA_D1
- I2CB_SCL
- J11_8
- J1_9
- J11_6
- J11_5
- J11_7
- FSIRXA_CLK
- SPIA_PTE
- CANB_TX
- J5_44/45
- J2_19
- J5_48
- J11_1
- J8_72
- SPIB_POCI
- EQEP1I
- SPIB_PICO
- J6_55
- J6_54
- J8_74
- J8_73

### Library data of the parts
C9 C18 C19 = CMP-0092309-1: Cap Ceramic 10uF 10V X5R 10% SMD 0603 85C Paper T/R; Manufacturer: YAGEO; Cap_F: 10µF; TempCo: 15%; Category 7542B8484461Ae85: Passive Components; Category 4C11811B7D3097D6: Single Components; SizeZ_mm: 1mm; Category F8883582C9A8234F: Capacitors; AEC Qualified: No; Value: 10µF; Category 85Ce48C4B2B95E09: Uncategorized
C10-C12 C14 C20-C22 = CMP-0090362-1: as C74 on sheet MCU133A_Connectors
C15 C16 = CMP-0007091-1: CAP, CERM, 2.2 uF, 10 V, +/- 10%, X5R, AEC-Q200 Grade 3, 0603; Manufacturer: TDK; TaMin_C: -55°C; Polarized: N; SizeAreaWB_mm2: 4.68; Value1: Unknown; U/M: EA; Value: 2.2uF; TaMax_C: 85°C; SizeZ_mm: 1; SizeX_mm: 1.6; SizeY_mm: 0.8; Value2: 10V; SizeArea_mm2: 1.28; AEC Qualified: Y; Cap_F: 2.2µF; AEC Grade: 3; AEC Category: Q200
C17 = CMP-0006228-2: CAP, CERM, 0.1 uF, 16 V, +/- 10%, X7R, 0402; Manufacturer: Wurth Elektronik; TaMin_C: -55°C; Polarized: N; SizeAreaWB_mm2: 3; Value1: Unknown; U/M: EA; Value: 0.1uF; TaMax_C: 125°C; SizeZ_mm: 0.6; SizeX_mm: 1; SizeY_mm: 0.5; Value2: 16V; Cap_F: 100nF; AEC Category: Q200
L2 = CMP-0003093-1: Ferrite Bead, 60 ohm @ 100 MHz, 3 A, 0805; Manufacturer: Wurth Elektronik; Ztyp@1GHz_Ohm: 95.384; ZTyp@100MHz_Ohm: 60; SizeAreaWB_mm2: 6.75; DCR_ohm: 0.025; Value1: 0.025 ohm; Imax_A: 3A; SizeZ_mm: 1.45; SizeX_mm: 2; SizeY_mm: 1.25; SizeArea_mm2: 2.5
L3 = CMP-0003073-1: Ferrite Bead, 220 ohm @ 100 MHz, 2 A, 0805; Manufacturer: Wurth Elektronik; Ztyp@1GHz_Ohm: 190.289; ZTyp@100MHz_Ohm: 220; SizeAreaWB_mm2: 6.75; DCR_ohm: 0.05; Value1: 0.05 ohm; Value: 220 ohm; Imax_A: 2A; SizeZ_mm: 1.45; SizeX_mm: 2; SizeY_mm: 1.25; SizeArea_mm2: 2.5
R10 R11 = CMP-0026890-5: RES, 2.2 k, 5%, 0.063 W, AEC-Q200 Grade 0, 0402; Manufacturer: Vishay-Dale; Value: 2.2k; Value_Code: 2k20; Power_W: 63mW; Value2: 0.063W; VDC_V: 50V; TempCo: 200 ppm/C; EIA_Code: E24; AEC Category: Q200; AEC Qualified: Y; AEC Grade: 0; SizeArea_mm2: 0.5; SizeX_mm: 1; SizeZ_mm: 0.6
R44 R45 R111 R112 = CMP-0027004-2: as R8 on sheet MCU133A_Connectors
R82 R83 = CMP-0026992-3: RES, 0, 5%, 0.1 W, AEC-Q200 Grade 0, 0402; Manufacturer: Panasonic; Power_W: 100mW; TempCo: 600 ppm/C; Value_Code: 0000; Value: 0; EIA_Code: E24; SizeX_mm: 1; SizeY_mm: 0.5; SizeZ_mm: 0.6; Value2: 0.1W; AEC Qualified: Y; VDC_V: 50V; AEC Category: Q200; SizeAreaWB_mm2: 3
S1 = CMP-0002328-1: Switch, SPST, 0.05 A, 12 VDC, SMD; Manufacturer: Diptronics; SizeAreaWB_mm2: 53.9; SizeArea_mm2: 27.3; SizeX_mm: 7.8; SizeY_mm: 3.5; VDC_V: 12V; PositionCount: 1; CurrentRating_mA: 50A
U1 = CMP-0043282-2: Real-Time Microcontroller, LQFP100; Manufacturer: Texas Instruments; SizeZ_mm: 1.6mm; AEC Qualified: No; Core Architecture: C28x; Data Bus Width: 32bits; Frequency_Fixed: 150MHz; Interface: I2C,SPI,UART,CAN,USB,LIN,SCI,SMBus; Max Supply Voltage: 3.63V; Memory Size: 1088KBytes; Memory Type: FLASH; Min Supply Voltage: 2.8V; Number Of A/D Converters: 5; Number Of Adc Channels: 35; Number Of Cores: 1; Number Of I/Os: 43; Number Of I2C Channels: 2; Number Of Pwm Channels: 24; Number Of Timers/Counters: 3; Ram Size: 133KBytes; Standoff Height: 0.05mm; TaMax_C: +125°C; TaMin_C: -40°C; TJmax_C: +150°C; AEC Category: Q200; CompType: IC

## Sheet MCU133A_ADC.SchDoc
size 431 x 279 mm; Date: Not shown in title block; ApprovedBy: Not shown in title block; CheckedBy: Not shown in title block; Author: Not shown in title block; CompanyName: Not shown in title block; Engineer: Not shown in title block; Organization: Not shown in title block; Address1: Not shown in title block; Address2: Not shown in title block; Address3: Not shown in title block; Address4: Not shown in title block; DocumentNumber: 5; Revision: Use project parameter SCH_Rev; SheetNumber: 5; SheetTotal: 8; PageSetup: Record=PageOptions¦CenterHorizontal=True¦CenterVertical=True¦PrintScale=1.00¦XCorrection=1.00¦YCorrection=1.00¦PrintKind=0¦BorderSize=5000000¦LeftOffset=0¦BottomOffset=0¦Orientation=2¦PaperLength=1000¦PaperWidth=1000¦Scale=100¦PaperSource=15¦PrintQuality=600¦MediaType=1¦DitherType=10¦PaperKind=Letter¦PrintScaleMode=1
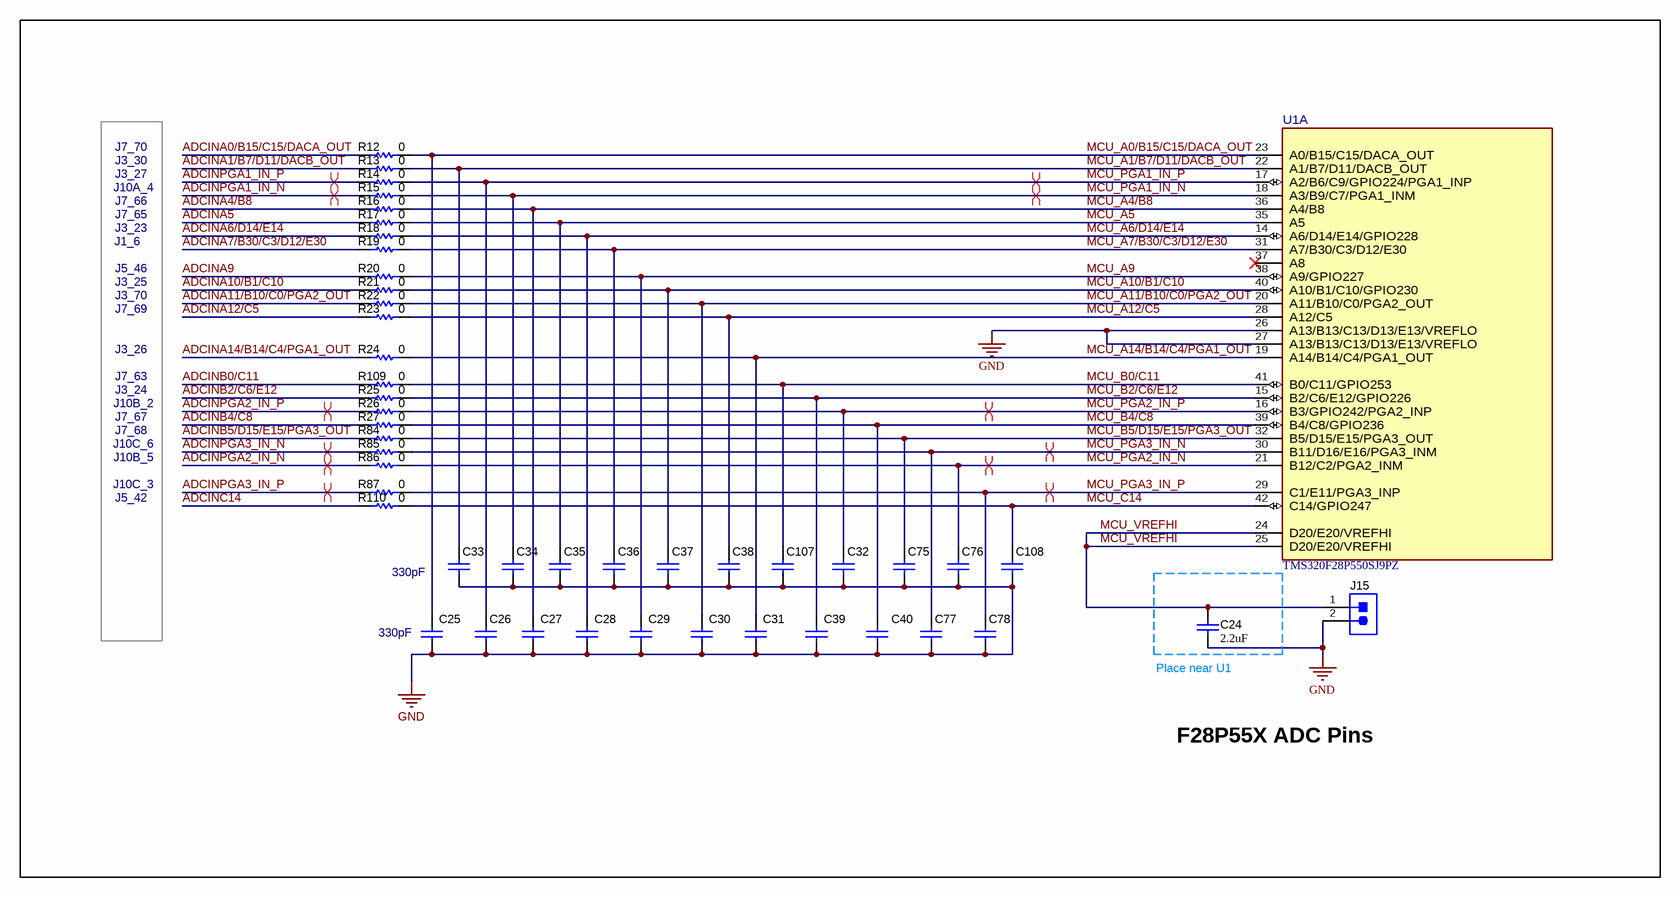
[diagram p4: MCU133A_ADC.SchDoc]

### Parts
C24  ValueDisplayed: 2.2uF  [0603]  (hidden comment: CGA3E3X5R1A225K080AB)
C25  GRM1555C1H331JA01D  [0402]  (value not drawn)
C26  value 330pF  [0402]  (hidden comment: GRM1555C1H331JA01D)
C27  GRM1555C1H331JA01D  [0402]  (value not drawn)
C28  GRM1555C1H331JA01D  [0402]  (value not drawn)
C29  GRM1555C1H331JA01D  [0402]  (value not drawn)
C30  GRM1555C1H331JA01D  [0402]  (value not drawn)
C31  GRM1555C1H331JA01D  [0402]  (value not drawn)
C32  GRM1555C1H331JA01D  [0402]  (value not drawn)
C33  value 330pF  [0402]  (hidden comment: GRM1555C1H331JA01D)
C34  GRM1555C1H331JA01D  [0402]  (value not drawn)
C35  GRM1555C1H331JA01D  [0402]  (value not drawn)
C36  GRM1555C1H331JA01D  [0402]  (value not drawn)
C37  GRM1555C1H331JA01D  [0402]  (value not drawn)
C38  GRM1555C1H331JA01D  [0402]  (value not drawn)
C39  GRM1555C1H331JA01D  [0402]  (value not drawn)
C40  GRM1555C1H331JA01D  [0402]  (value not drawn)
C75  GRM1555C1H331JA01D  [0402]  (value not drawn)
C76  GRM1555C1H331JA01D  [0402]  (value not drawn)
C77  GRM1555C1H331JA01D  [0402]  (value not drawn)
C78  GRM1555C1H331JA01D  [0402]  (value not drawn)
C107  GRM1555C1H331JA01D  [0402]  (value not drawn)
C108  GRM1555C1H331JA01D  [0402]  (value not drawn)
J15  61300211121  [WURTH_61300211121]  (value not drawn)
R12  ValueDisplayed: 0  [0402]  (hidden comment: RC0402JR-070RL)
R13  ValueDisplayed: 0  [0402]  (hidden comment: RC0402JR-070RL)
R14  ValueDisplayed: 0  [0402]  (hidden comment: RC0402JR-070RL)
R15  ValueDisplayed: 0  [0402]  (hidden comment: RC0402JR-070RL)
R16  ValueDisplayed: 0  [0402]  (hidden comment: RC0402JR-070RL)
R17  ValueDisplayed: 0  [0402]  (hidden comment: RC0402JR-070RL)
R18  ValueDisplayed: 0  [0402]  (hidden comment: RC0402JR-070RL)
R19  ValueDisplayed: 0  [0402]  (hidden comment: RC0402JR-070RL)
R20  ValueDisplayed: 0  [0402]  (hidden comment: RC0402JR-070RL)
R21  ValueDisplayed: 0  [0402]  (hidden comment: RC0402JR-070RL)
R22  ValueDisplayed: 0  [0402]  (hidden comment: RC0402JR-070RL)
R23  ValueDisplayed: 0  [0402]  (hidden comment: RC0402JR-070RL)
R24  ValueDisplayed: 0  [0402]  (hidden comment: RC0402JR-070RL)
R25  ValueDisplayed: 0  [0402]  (hidden comment: RC0402JR-070RL)
R26  ValueDisplayed: 0  [0402]  (hidden comment: RC0402JR-070RL)
R27  ValueDisplayed: 0  [0402]  (hidden comment: RC0402JR-070RL)
R84  ValueDisplayed: 0  [0402]  (hidden comment: RC0402JR-070RL)
R85  ValueDisplayed: 0  [0402]  (hidden comment: RC0402JR-070RL)
R86  ValueDisplayed: 0  [0402]  (hidden comment: RC0402JR-070RL)
R87  ValueDisplayed: 0  [0402]  (hidden comment: RC0402JR-070RL)
R109  ValueDisplayed: 0  [0402]  (hidden comment: RC0402JR-070RL)
R110  ValueDisplayed: 0  [0402]  (hidden comment: RC0402JR-070RL)
U1  TMS320F28P550SJ9PZ  [PZ0100A-MFG]  (part A of 4)

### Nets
GND: C24.2 C25.2 C26.2 C27.2 C28.2 C29.2 C30.2 C31.2 C32.2 C33.2 C34.2 C35.2 C36.2 C37.2 C38.2 C39.2 C40.2 C75.2 C76.2 C77.2 C78.2 C107.2 C108.2 J15.2 U1.26(A13/B13/C13/D13/E13/VREFLO) U1.27(A13/B13/C13/D13/E13/VREFLO)
ADCINA0/B15/C15/DACA_OUT: R12.1
ADCINA1/B7/D11/DACB_OUT: R13.1
ADCINA4/B8: R16.1
ADCINA5: R17.1
ADCINA6/D14/E14: R18.1
ADCINA7/B30/C3/D12/E30: R19.1
ADCINA9: R20.1
ADCINA10/B1/C10: R21.1
ADCINA11/B10/C0/PGA2_OUT: R22.1
ADCINA12/C5: R23.1
ADCINA14/B14/C4/PGA1_OUT: R24.1
ADCINB0/C11: R109.1
ADCINB2/C6/E12: R25.1
ADCINB4/C8: R27.1
ADCINB5/D15/E15/PGA3_OUT: R84.1
ADCINC14: R110.1
ADCINPGA1_IN_N: R15.1
ADCINPGA1_IN_P: R14.1
ADCINPGA2_IN_N: R86.1
ADCINPGA2_IN_P: R26.1
ADCINPGA3_IN_N: R85.1
ADCINPGA3_IN_P: R87.1
MCU_A0/B15/C15/DACA_OUT: C25.1 R12.2 U1.23(A0/B15/C15/DACA_OUT)
MCU_A1/B7/D11/DACB_OUT: C33.1 R13.2 U1.22(A1/B7/D11/DACB_OUT)
MCU_A4/B8: C27.1 R16.2 U1.36(A4/B8)
MCU_A5: C35.1 R17.2 U1.35(A5)
MCU_A6/D14/E14: C28.1 R18.2 U1.14(A6/D14/E14/GPIO228)
MCU_A7/B30/C3/D12/E30: C36.1 R19.2 U1.31(A7/B30/C3/D12/E30)
MCU_A9: C29.1 R20.2 U1.38(A9/GPIO227)
MCU_A10/B1/C10: C37.1 R21.2 U1.40(A10/B1/C10/GPIO230)
MCU_A11/B10/C0/PGA2_OUT: C30.1 R22.2 U1.20(A11/B10/C0/PGA2_OUT)
MCU_A12/C5: C38.1 R23.2 U1.28(A12/C5)
MCU_A14/B14/C4/PGA1_OUT: C31.1 R24.2 U1.19(A14/B14/C4/PGA1_OUT)
MCU_B0/C11: C107.1 R109.2 U1.41(B0/C11/GPIO253)
MCU_B2/C6/E12: C39.1 R25.2 U1.15(B2/C6/E12/GPIO226)
MCU_B4/C8: C40.1 R27.2 U1.39(B4/C8/GPIO236)
MCU_B5/D15/E15/PGA3_OUT: C75.1 R84.2 U1.32(B5/D15/E15/PGA3_OUT)
MCU_C14: C108.1 R110.2 U1.42(C14/GPIO247)
MCU_PGA1_IN_N: C34.1 R15.2 U1.18(A3/B9/C7/PGA1_INM)
MCU_PGA1_IN_P: C26.1 R14.2 U1.17(A2/B6/C9/GPIO224/PGA1_INP)
MCU_PGA2_IN_N: C76.1 R86.2 U1.21(B12/C2/PGA2_INM)
MCU_PGA2_IN_P: C32.1 R26.2 U1.16(B3/GPIO242/PGA2_INP)
MCU_PGA3_IN_N: C77.1 R85.2 U1.30(B11/D16/E16/PGA3_INM)
MCU_PGA3_IN_P: C78.1 R87.2 U1.29(C1/E11/PGA3_INP)
MCU_VREFHI: C24.1 J15.1 U1.24(D20/E20/VREFHI) U1.25(D20/E20/VREFHI)

Not connected (* = marked no-connect by the designer): U1 37(A8)*

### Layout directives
differential pair: ADCINPGA1_IN_N, ADCINPGA1_IN_P, ADCINPGA2_IN_N, ADCINPGA2_IN_P, ADCINPGA3_IN_N, ADCINPGA3_IN_P, MCU_PGA1_IN_N, MCU_PGA1_IN_P, MCU_PGA2_IN_N, MCU_PGA2_IN_P, MCU_PGA3_IN_N, MCU_PGA3_IN_P

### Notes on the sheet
- J7_70
- J7_65
- J7_66
- J3_30
- J3_27
- J10A_4
- J1_6
- J3_25
- J3_23
- J5_46
- J3_26
- J7_69
- J3_70
- J7_67
- J7_63
- J3_24
- J10B_2
- J7_68
- J10C_3
- J10B_5
- J10C_6
- J5_42
- (near C24) Place near U1
- F28P55X ADC Pins

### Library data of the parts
C24 = CMP-0007091-1: as C15 on sheet MCU133A_F28P55x_Device
C25 C27-C32 C34-C40 C75-C78 C107 C108 = CMP-0006456-2: CAP, CERM, 330 pF, 50 V, +/- 5%, C0G/NP0, 0402; Manufacturer: MuRata; TaMin_C: -55°C; Polarized: N; SizeAreaWB_mm2: 3; Value1: Unknown; U/M: EA; Value: 330pF; TaMax_C: 125°C; SizeZ_mm: 0.6; SizeX_mm: 1; SizeY_mm: 0.5; Value2: 50V; AEC Category: Q200
C26 C33 = CMP-0006456-2: CAP, CERM, 330 pF, 50 V, +/- 5%, C0G/NP0, 0402; Manufacturer: MuRata; TaMin_C: -55°C; Polarized: N; SizeAreaWB_mm2: 3; Value1: Unknown; U/M: EA; TaMax_C: 125°C; SizeZ_mm: 0.6; SizeX_mm: 1; SizeY_mm: 0.5; Value2: 50V; AEC Category: Q200
J15 = CMP-0054794-1: as JP9 on sheet MCU133A_Connectors
R12-R27 R84-R87 R109 R110 = CMP-0027004-2: as R8 on sheet MCU133A_Connectors
U1 = CMP-0043282-2: as U1 on sheet MCU133A_F28P55x_Device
